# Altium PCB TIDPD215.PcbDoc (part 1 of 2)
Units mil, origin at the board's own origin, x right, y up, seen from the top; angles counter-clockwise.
Board outline 3200 x 2750 mil, 6 copper layers (Top Layer, Layer 2 - GND, Layer 3 - Power, Layer 4 - VPOS B/C, VNEG B/D, Layer 5 - VPOS A/D, VNEG A/C, Bottom Layer), stack 97.668 mil thick; 154 components, 79 nets, 389 pads, 279 vias.
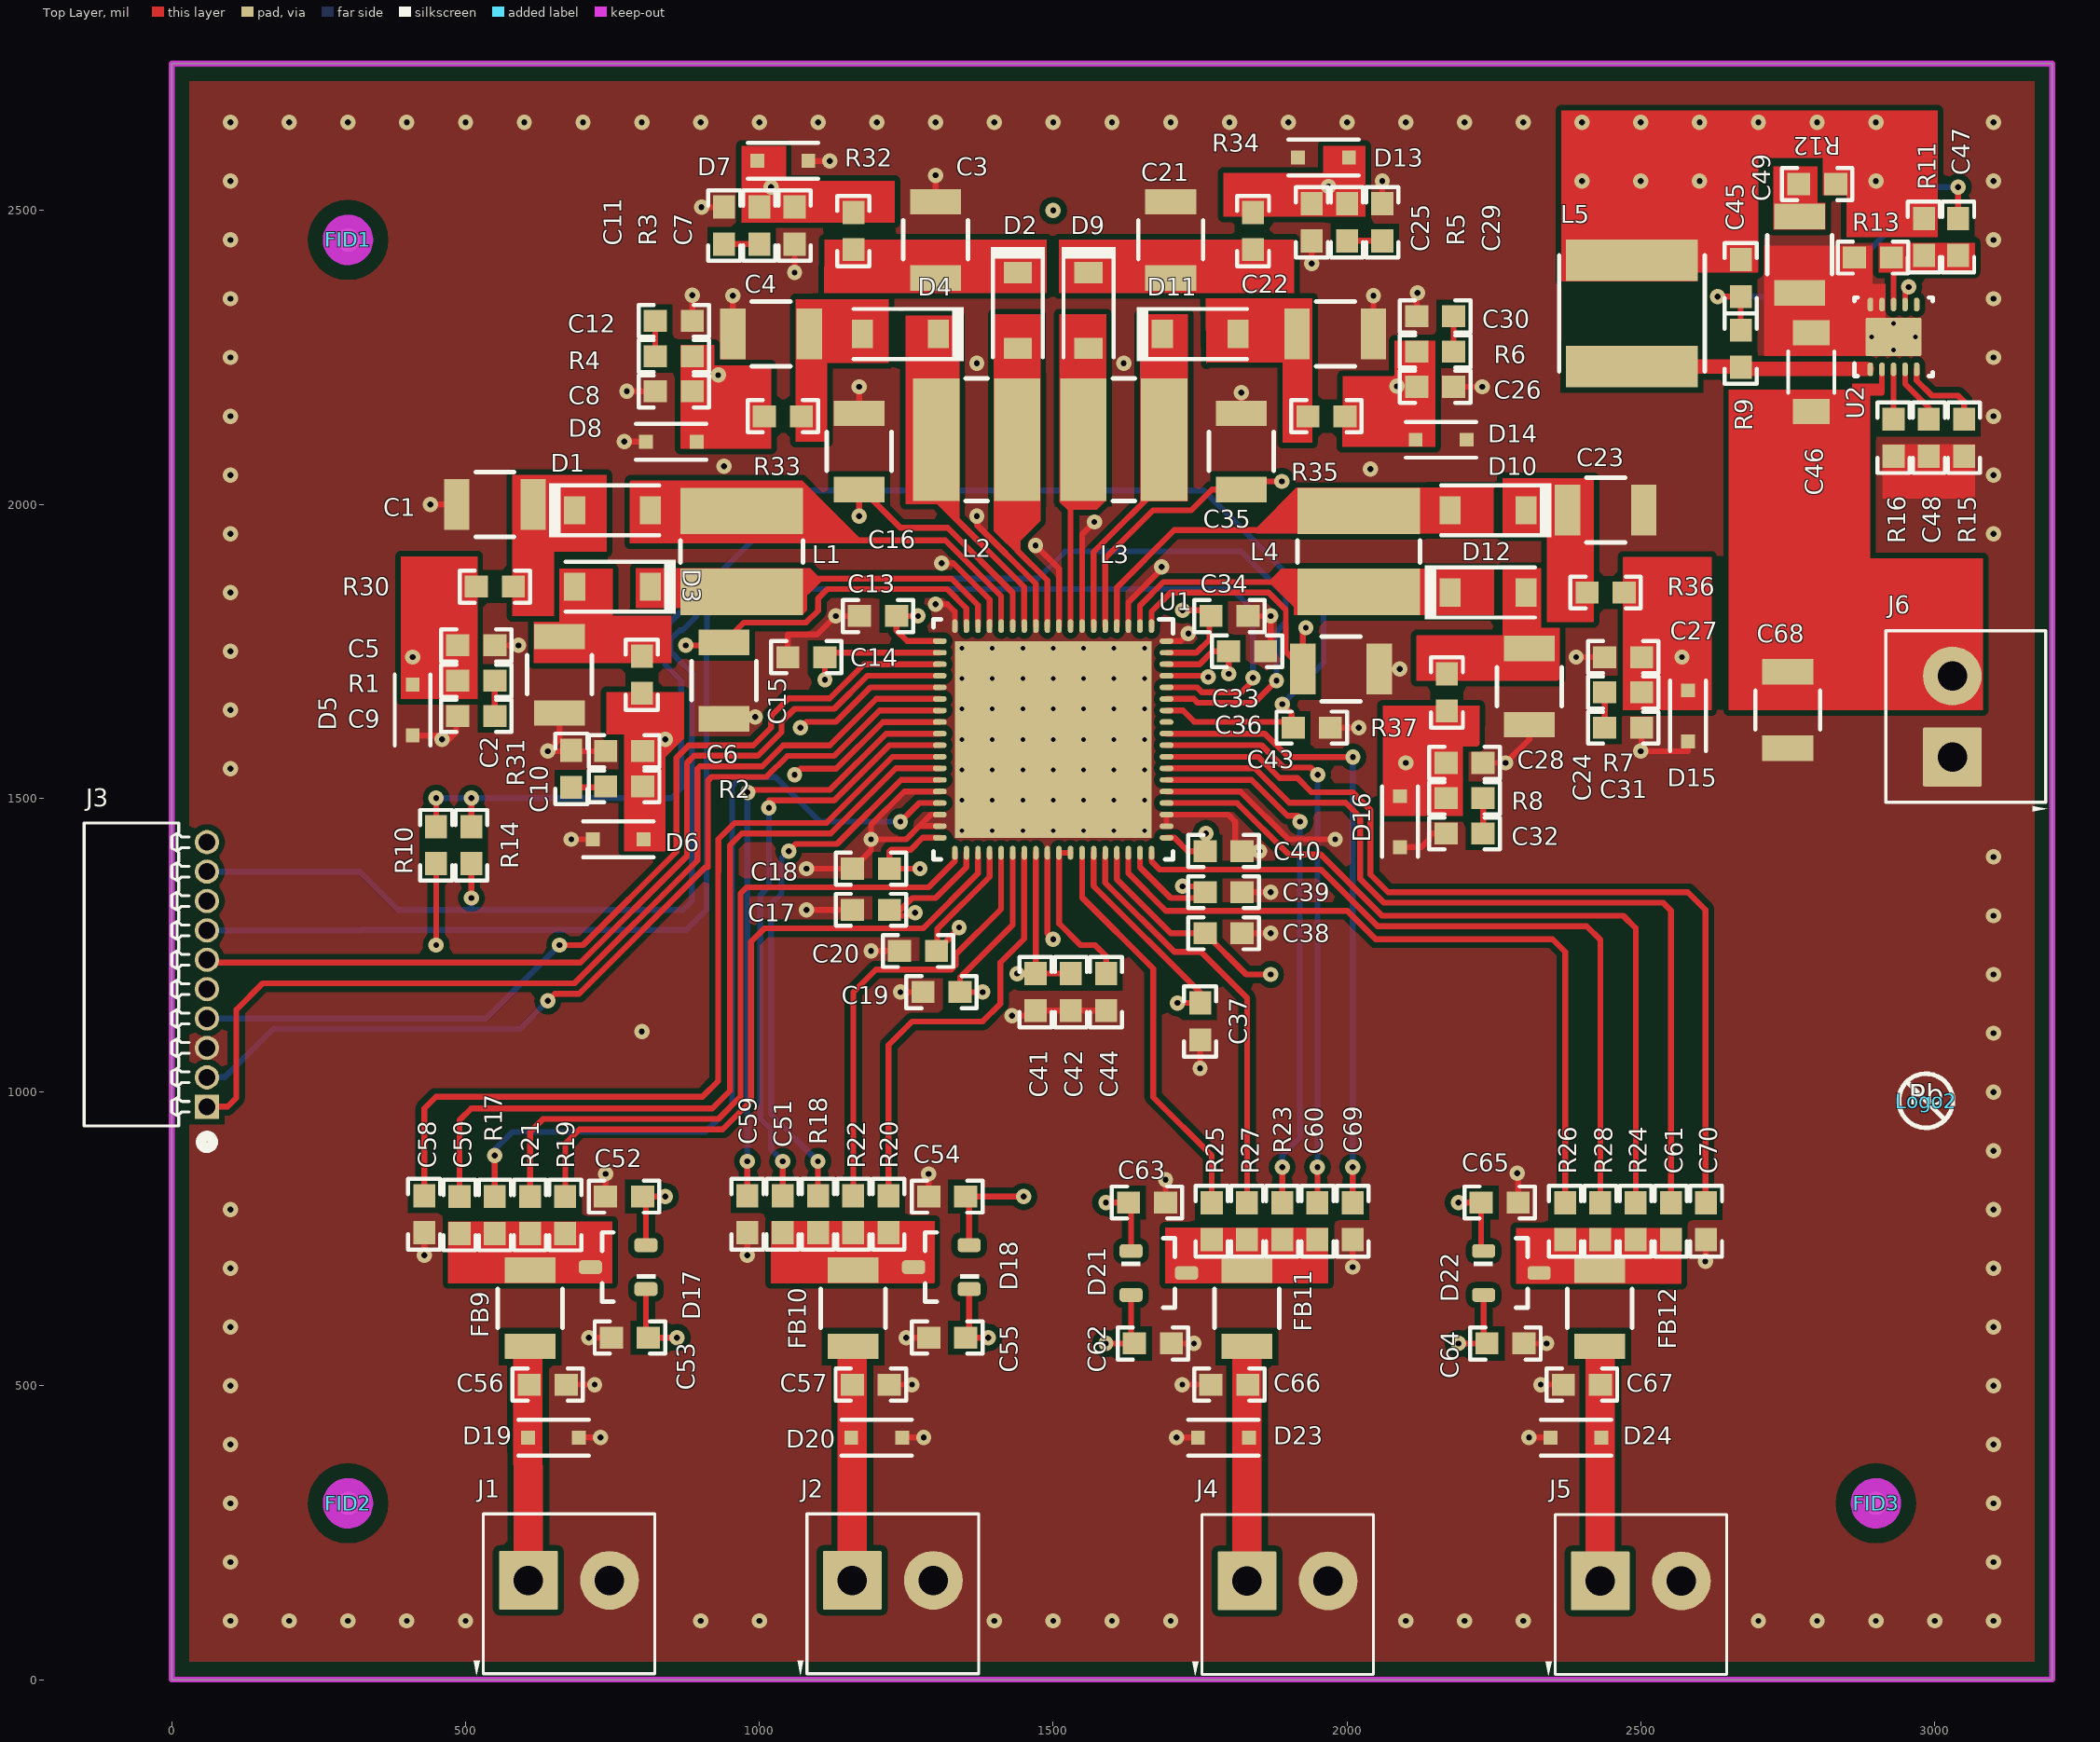
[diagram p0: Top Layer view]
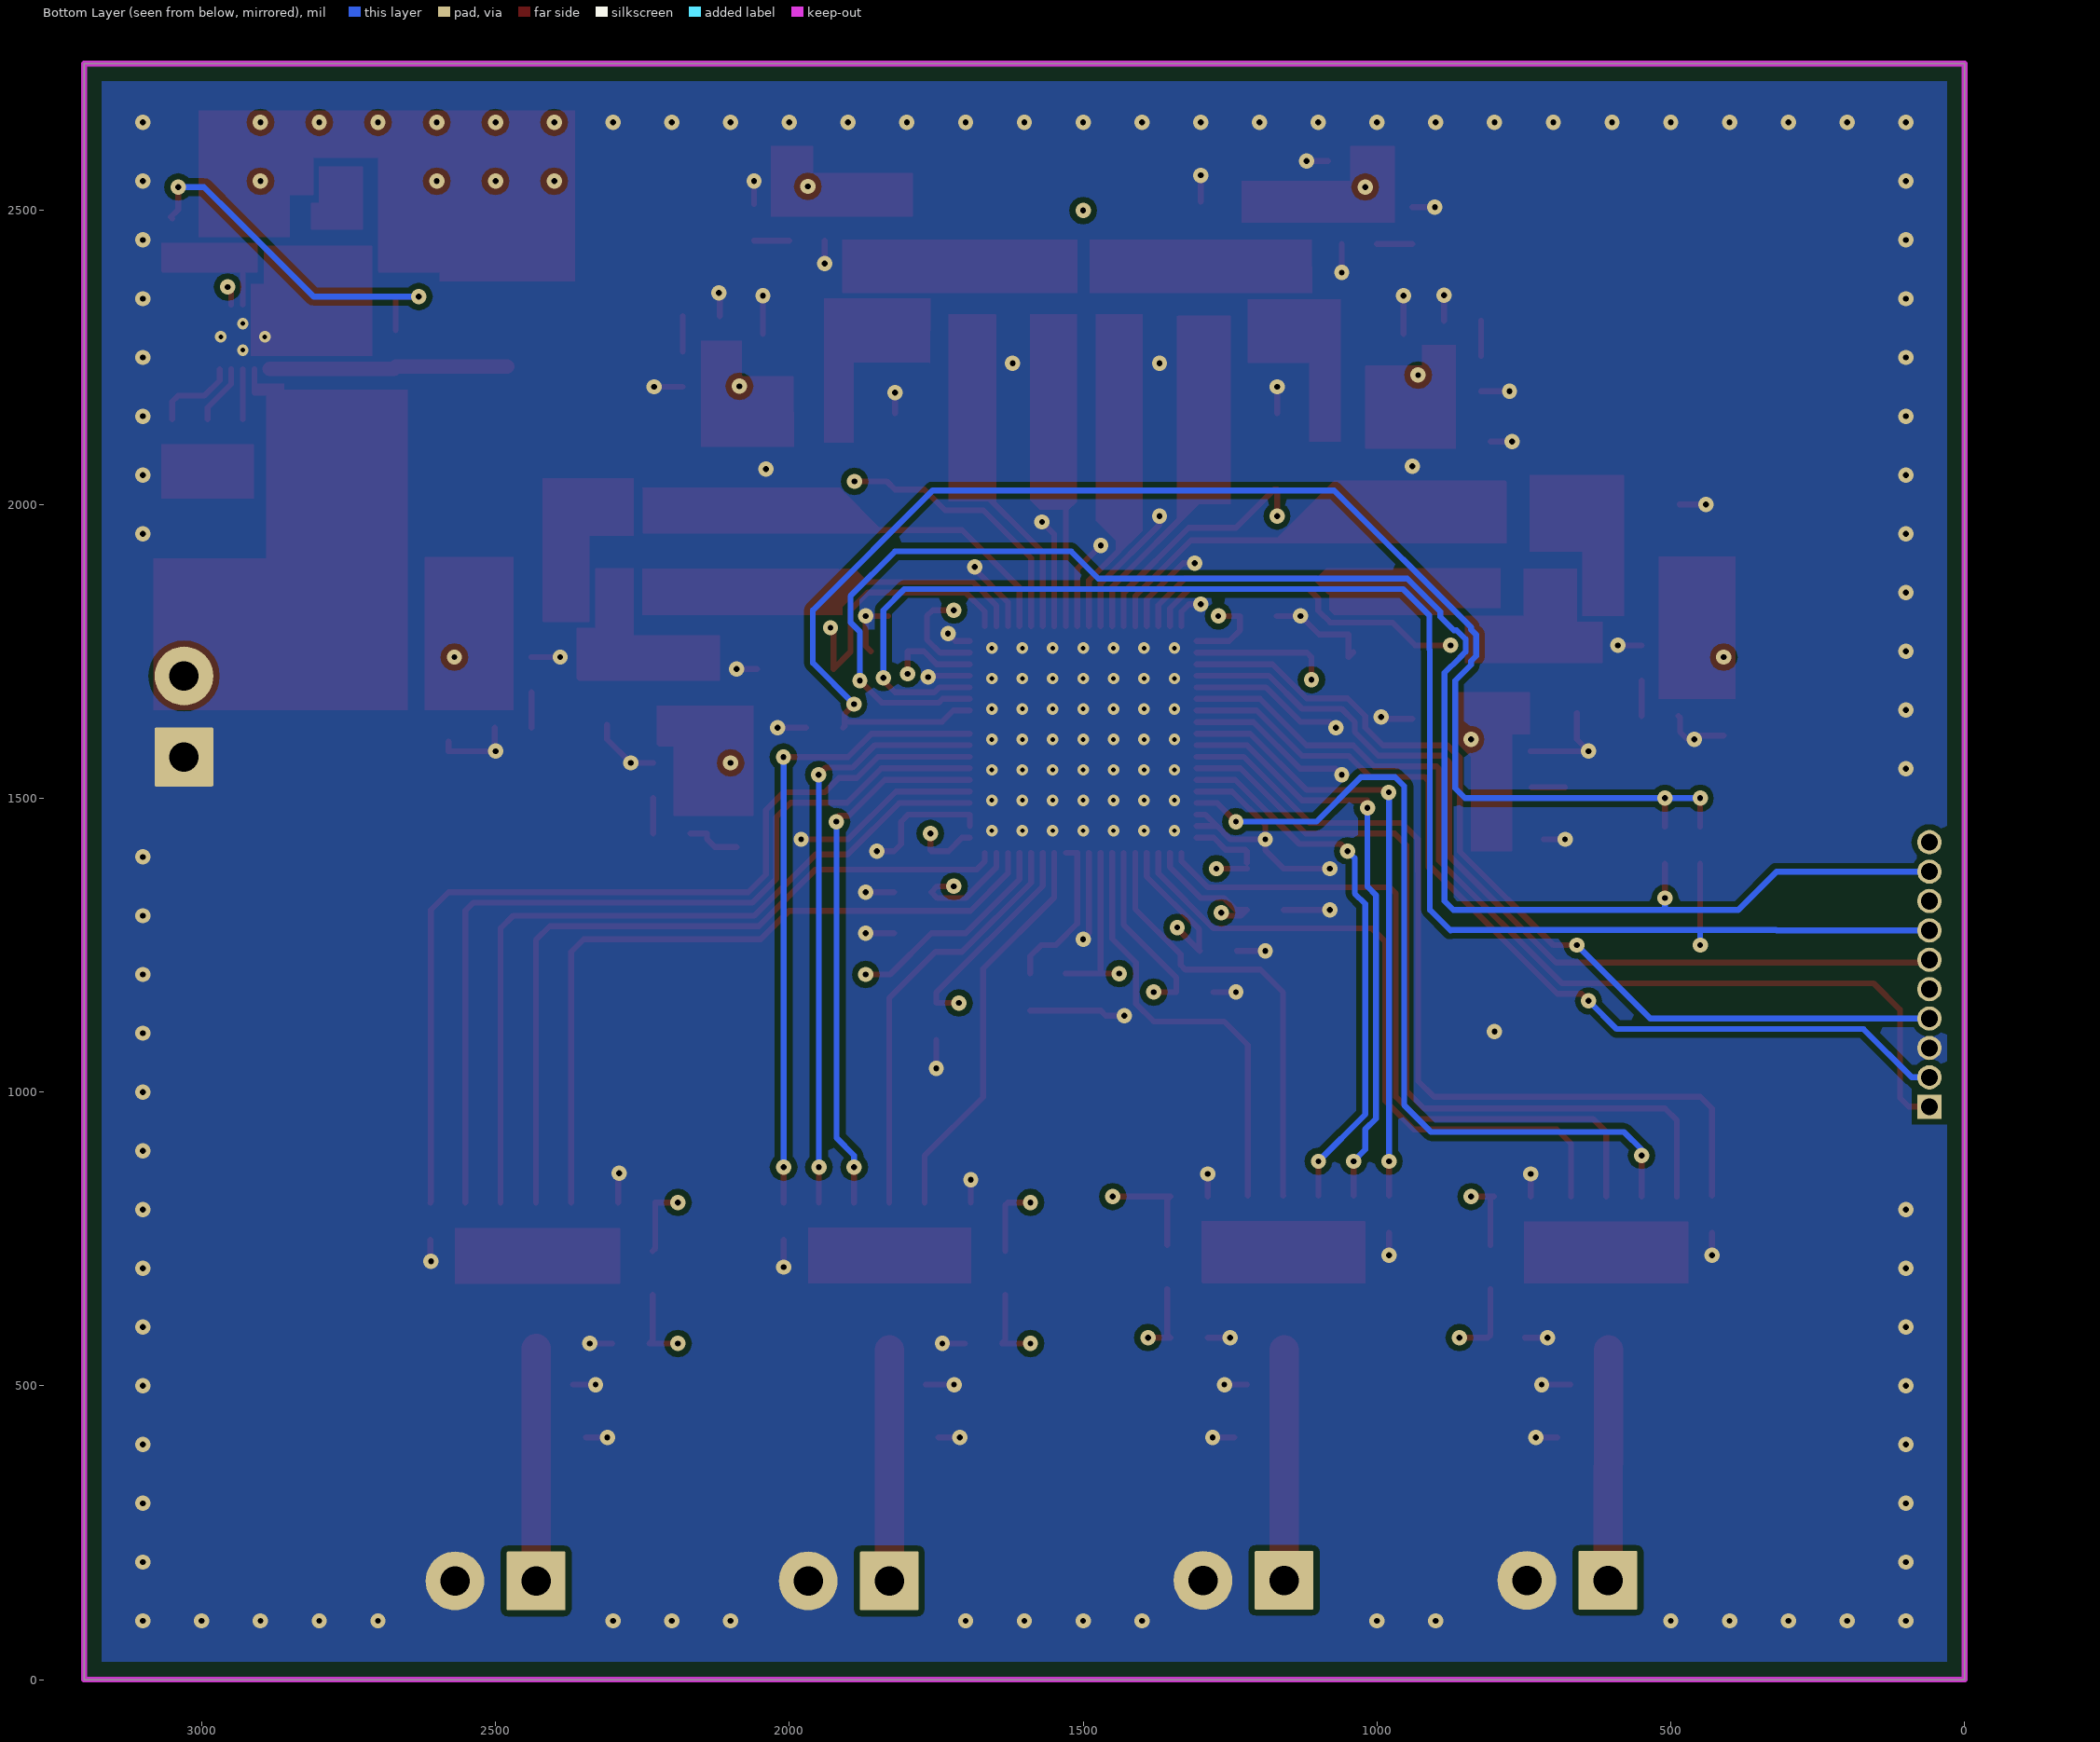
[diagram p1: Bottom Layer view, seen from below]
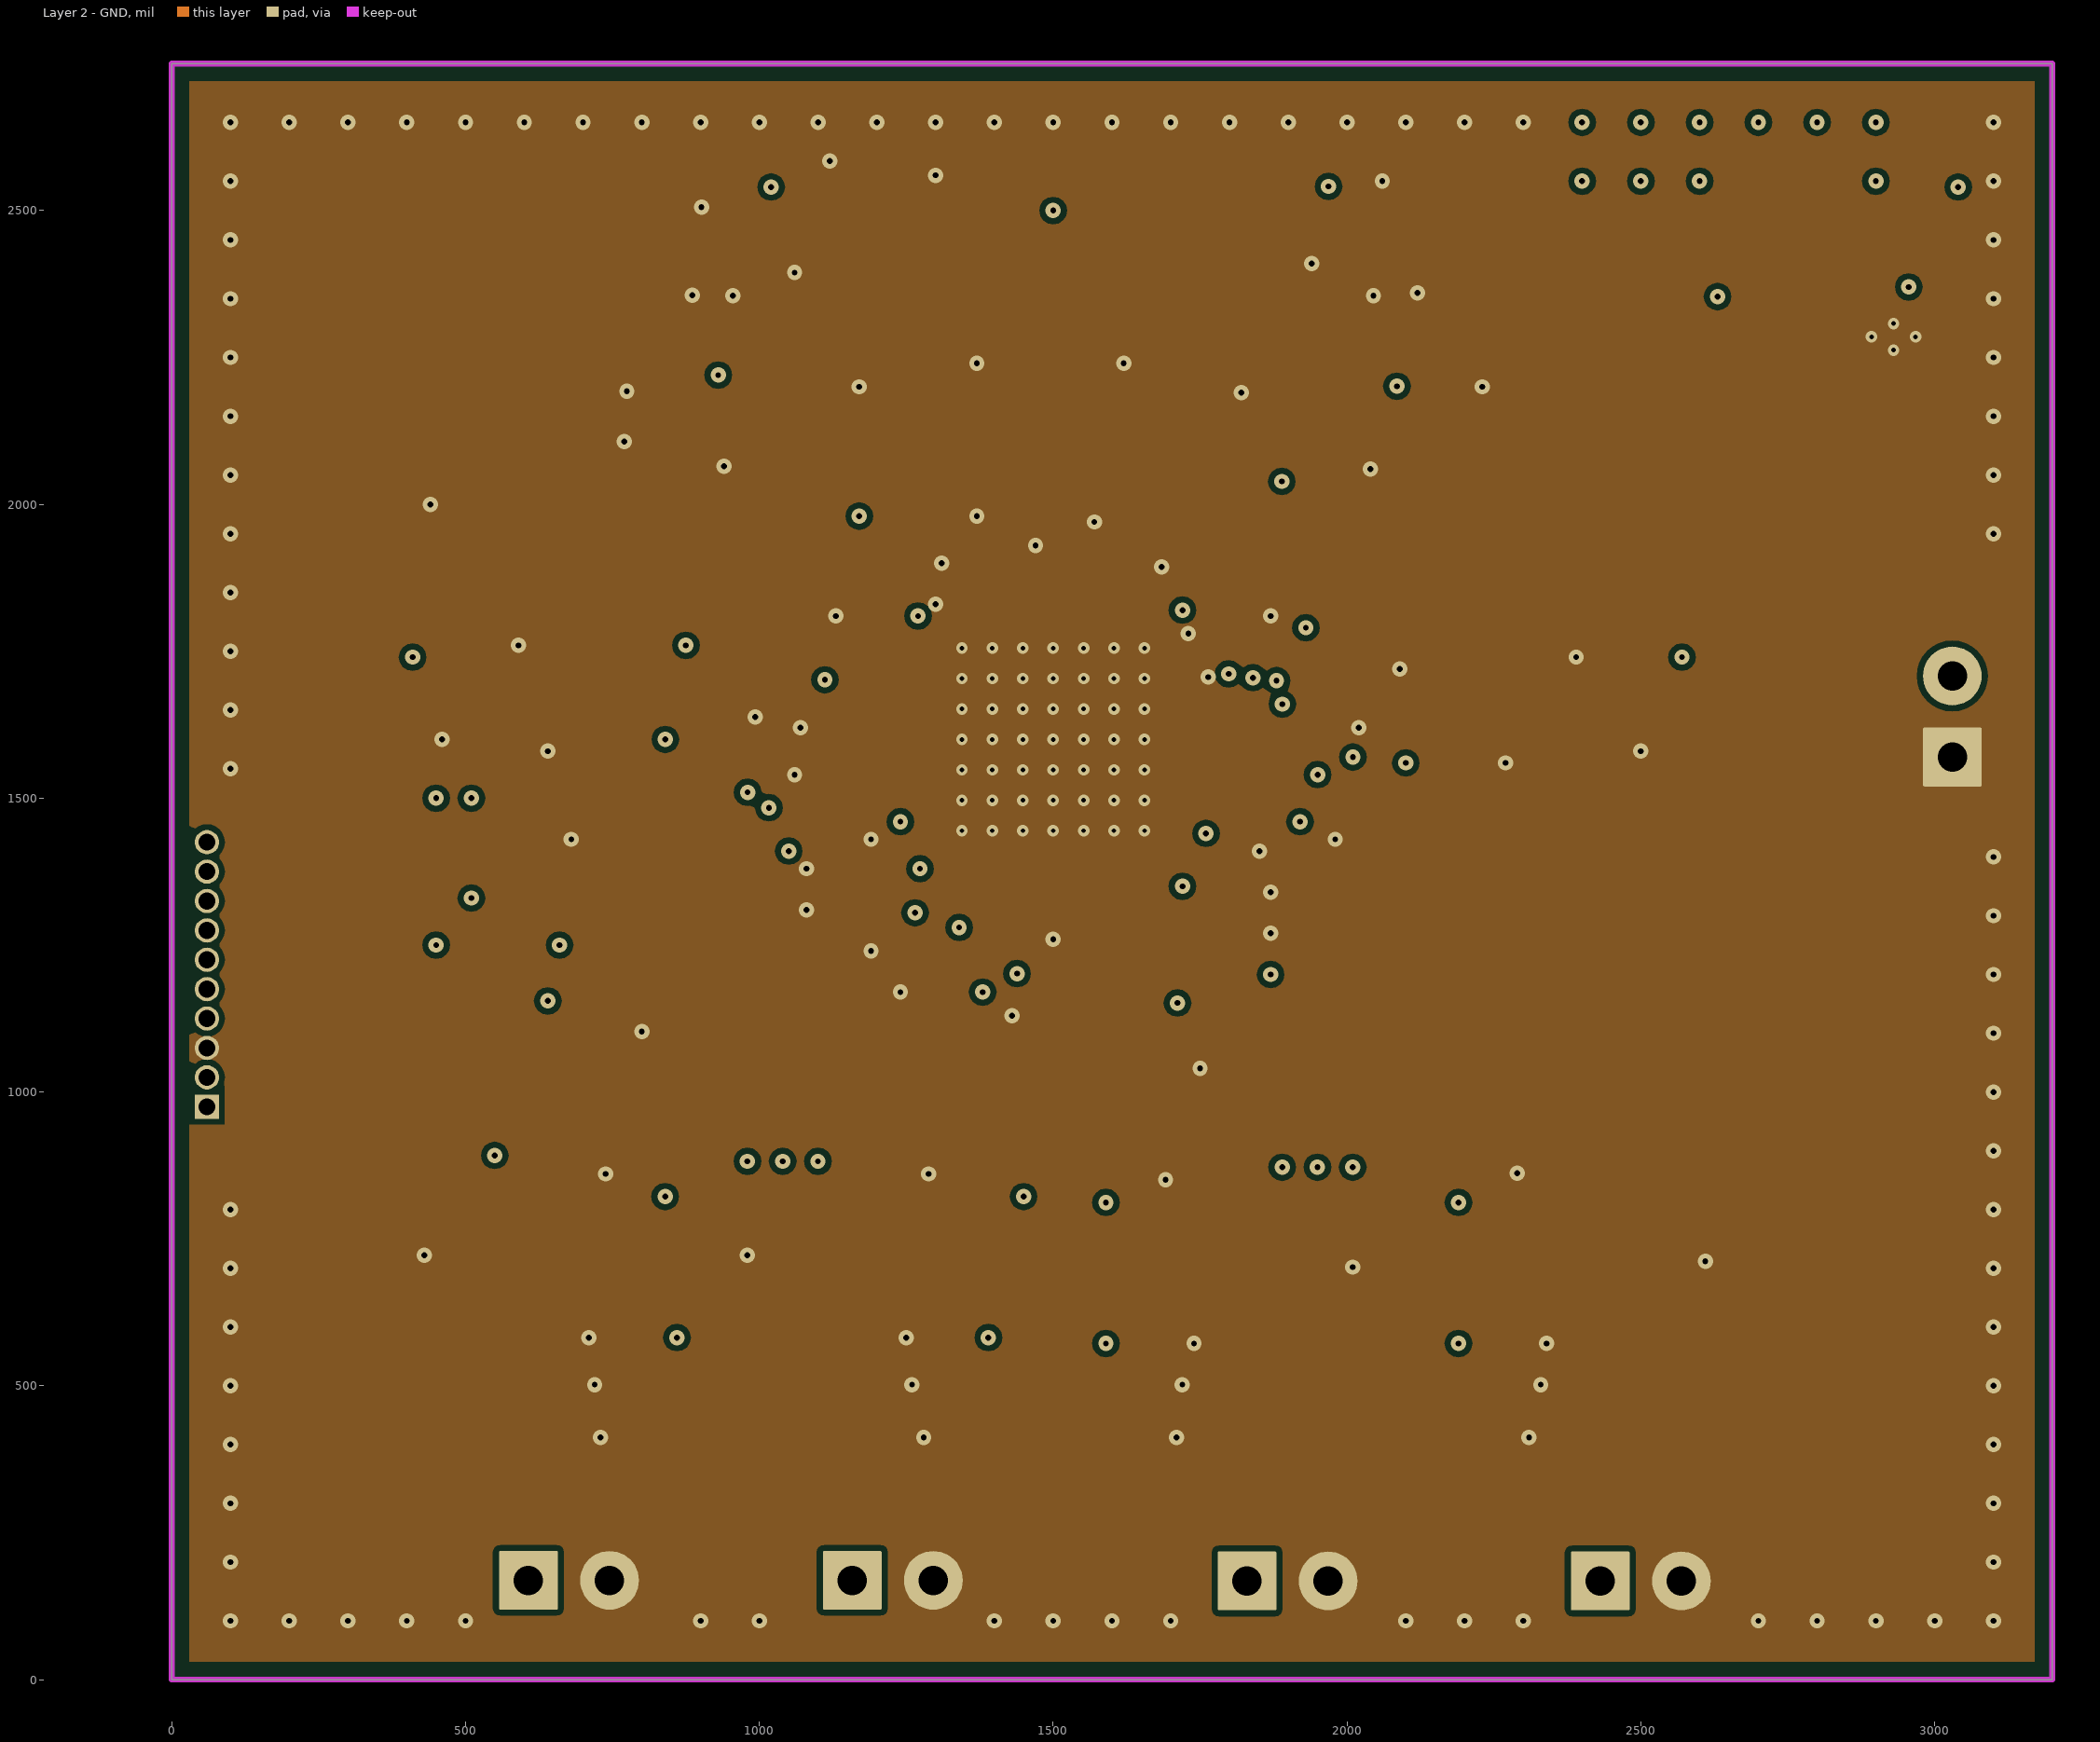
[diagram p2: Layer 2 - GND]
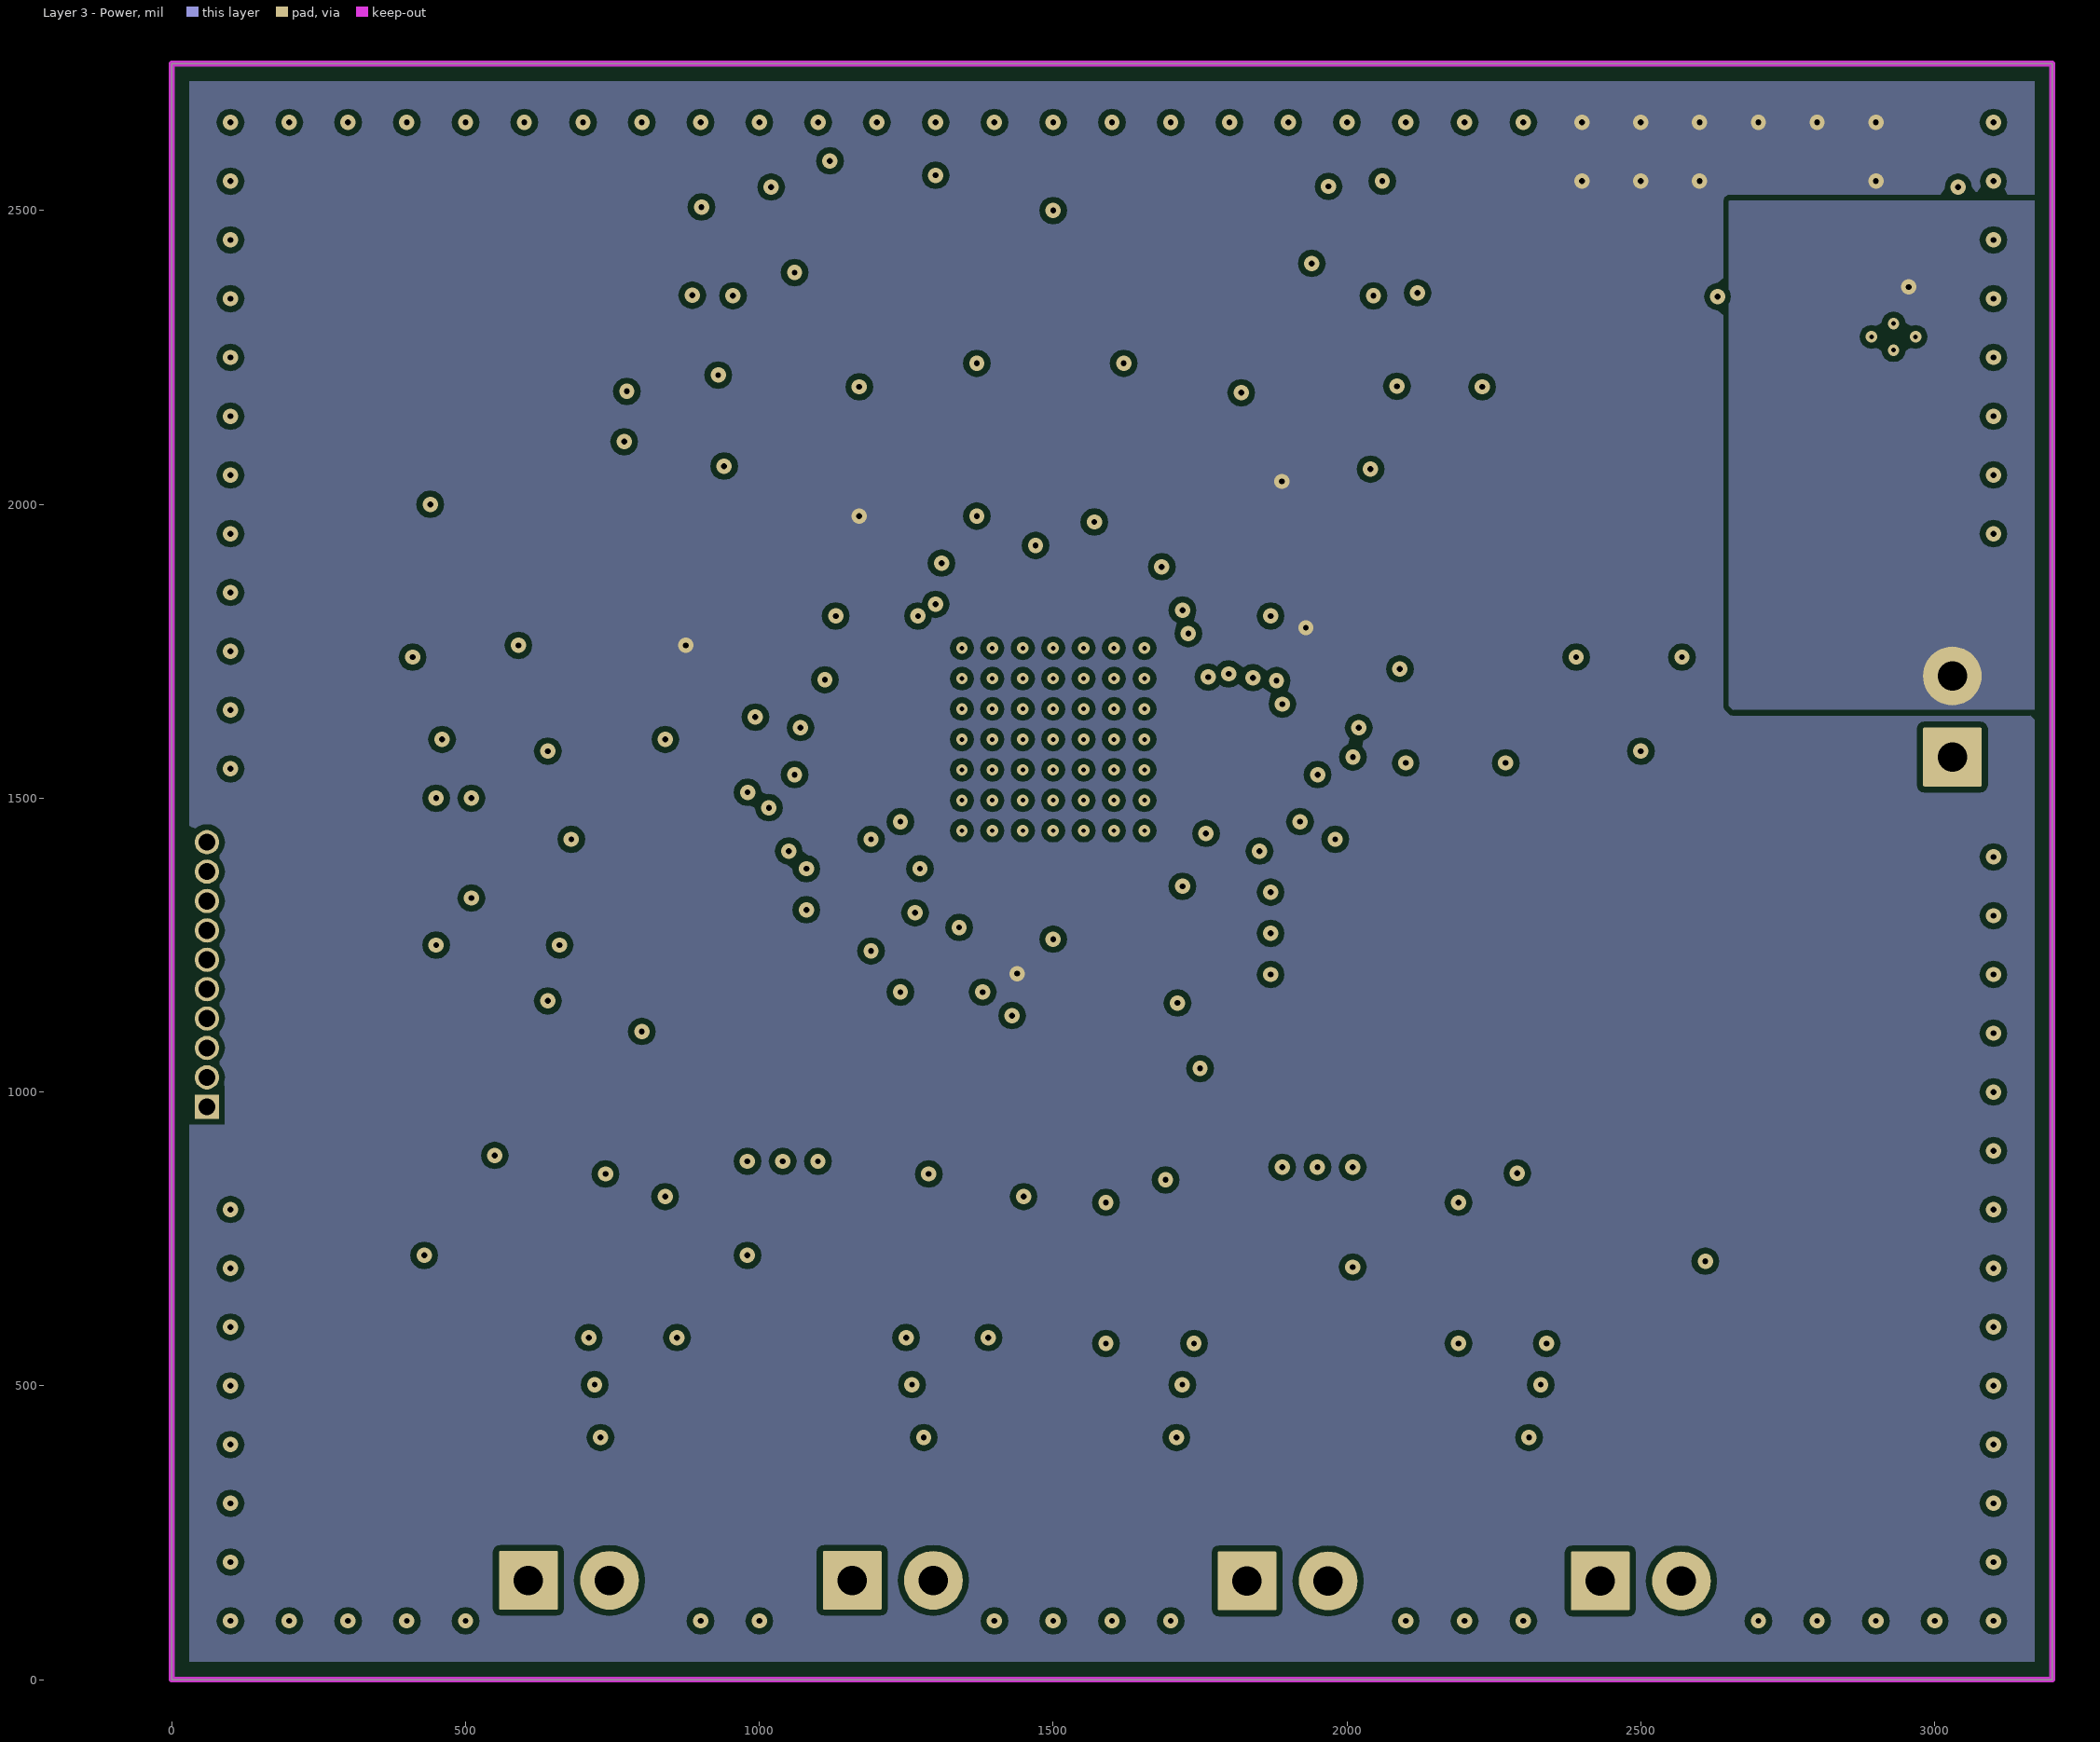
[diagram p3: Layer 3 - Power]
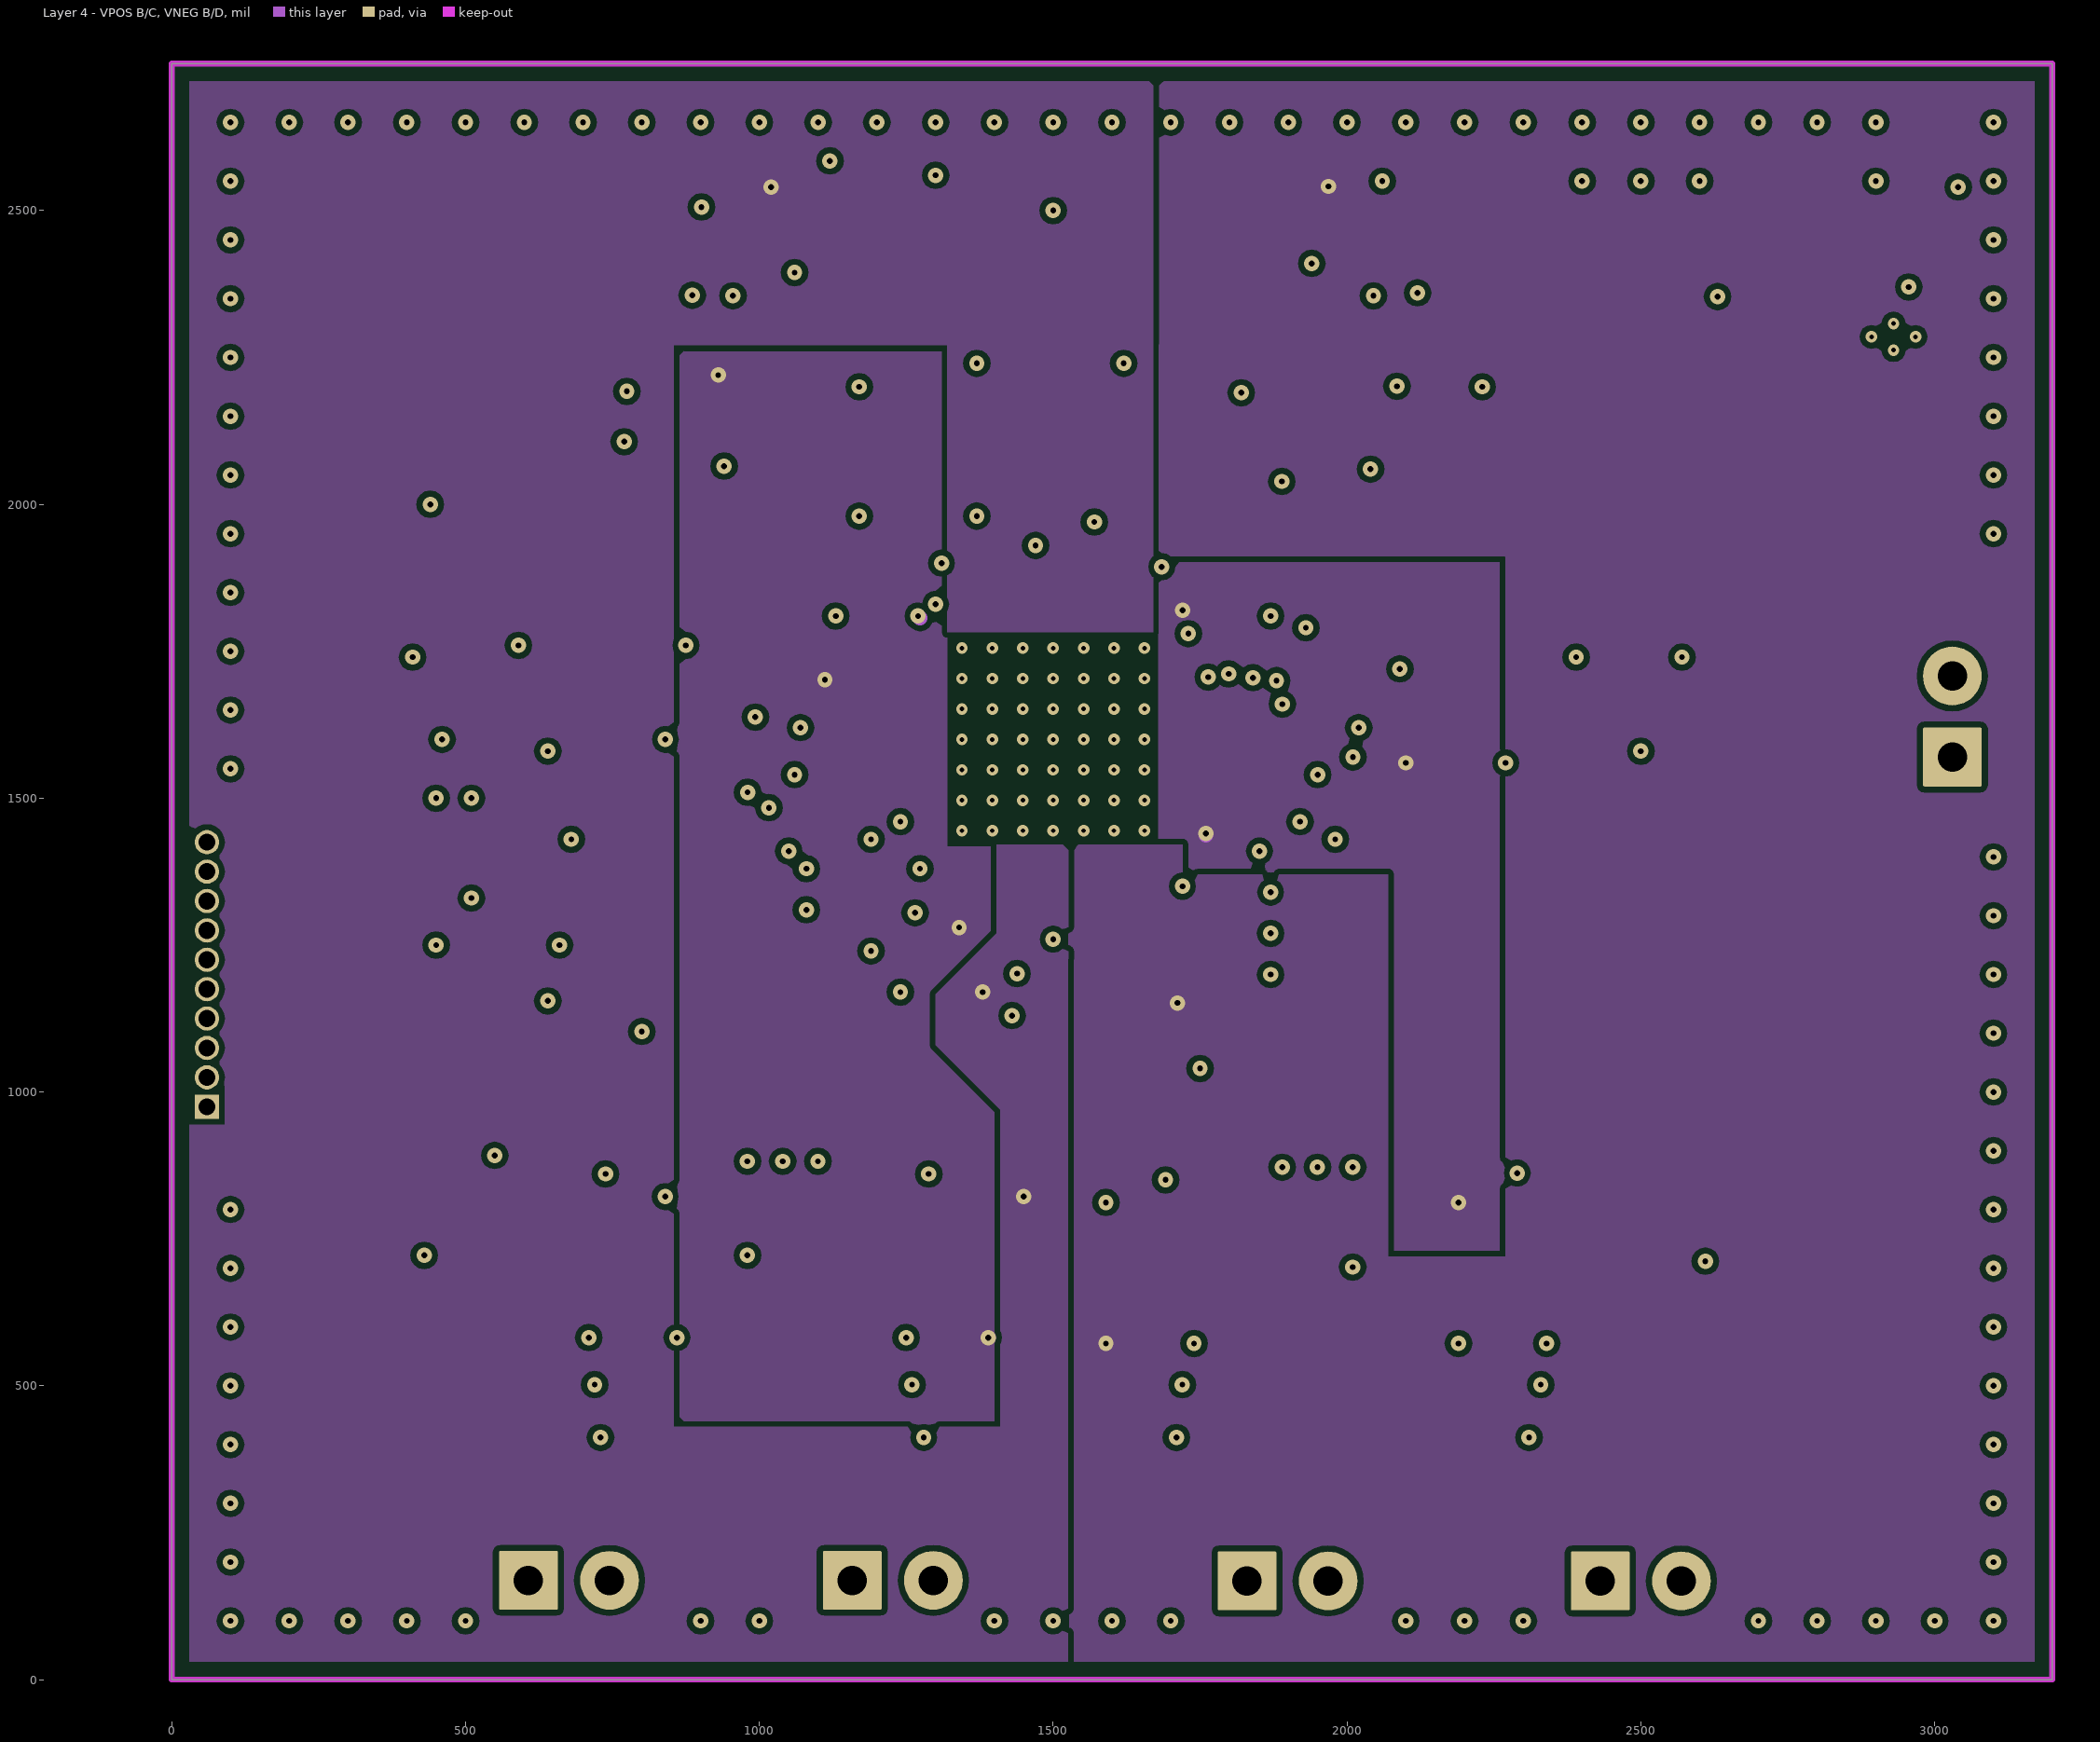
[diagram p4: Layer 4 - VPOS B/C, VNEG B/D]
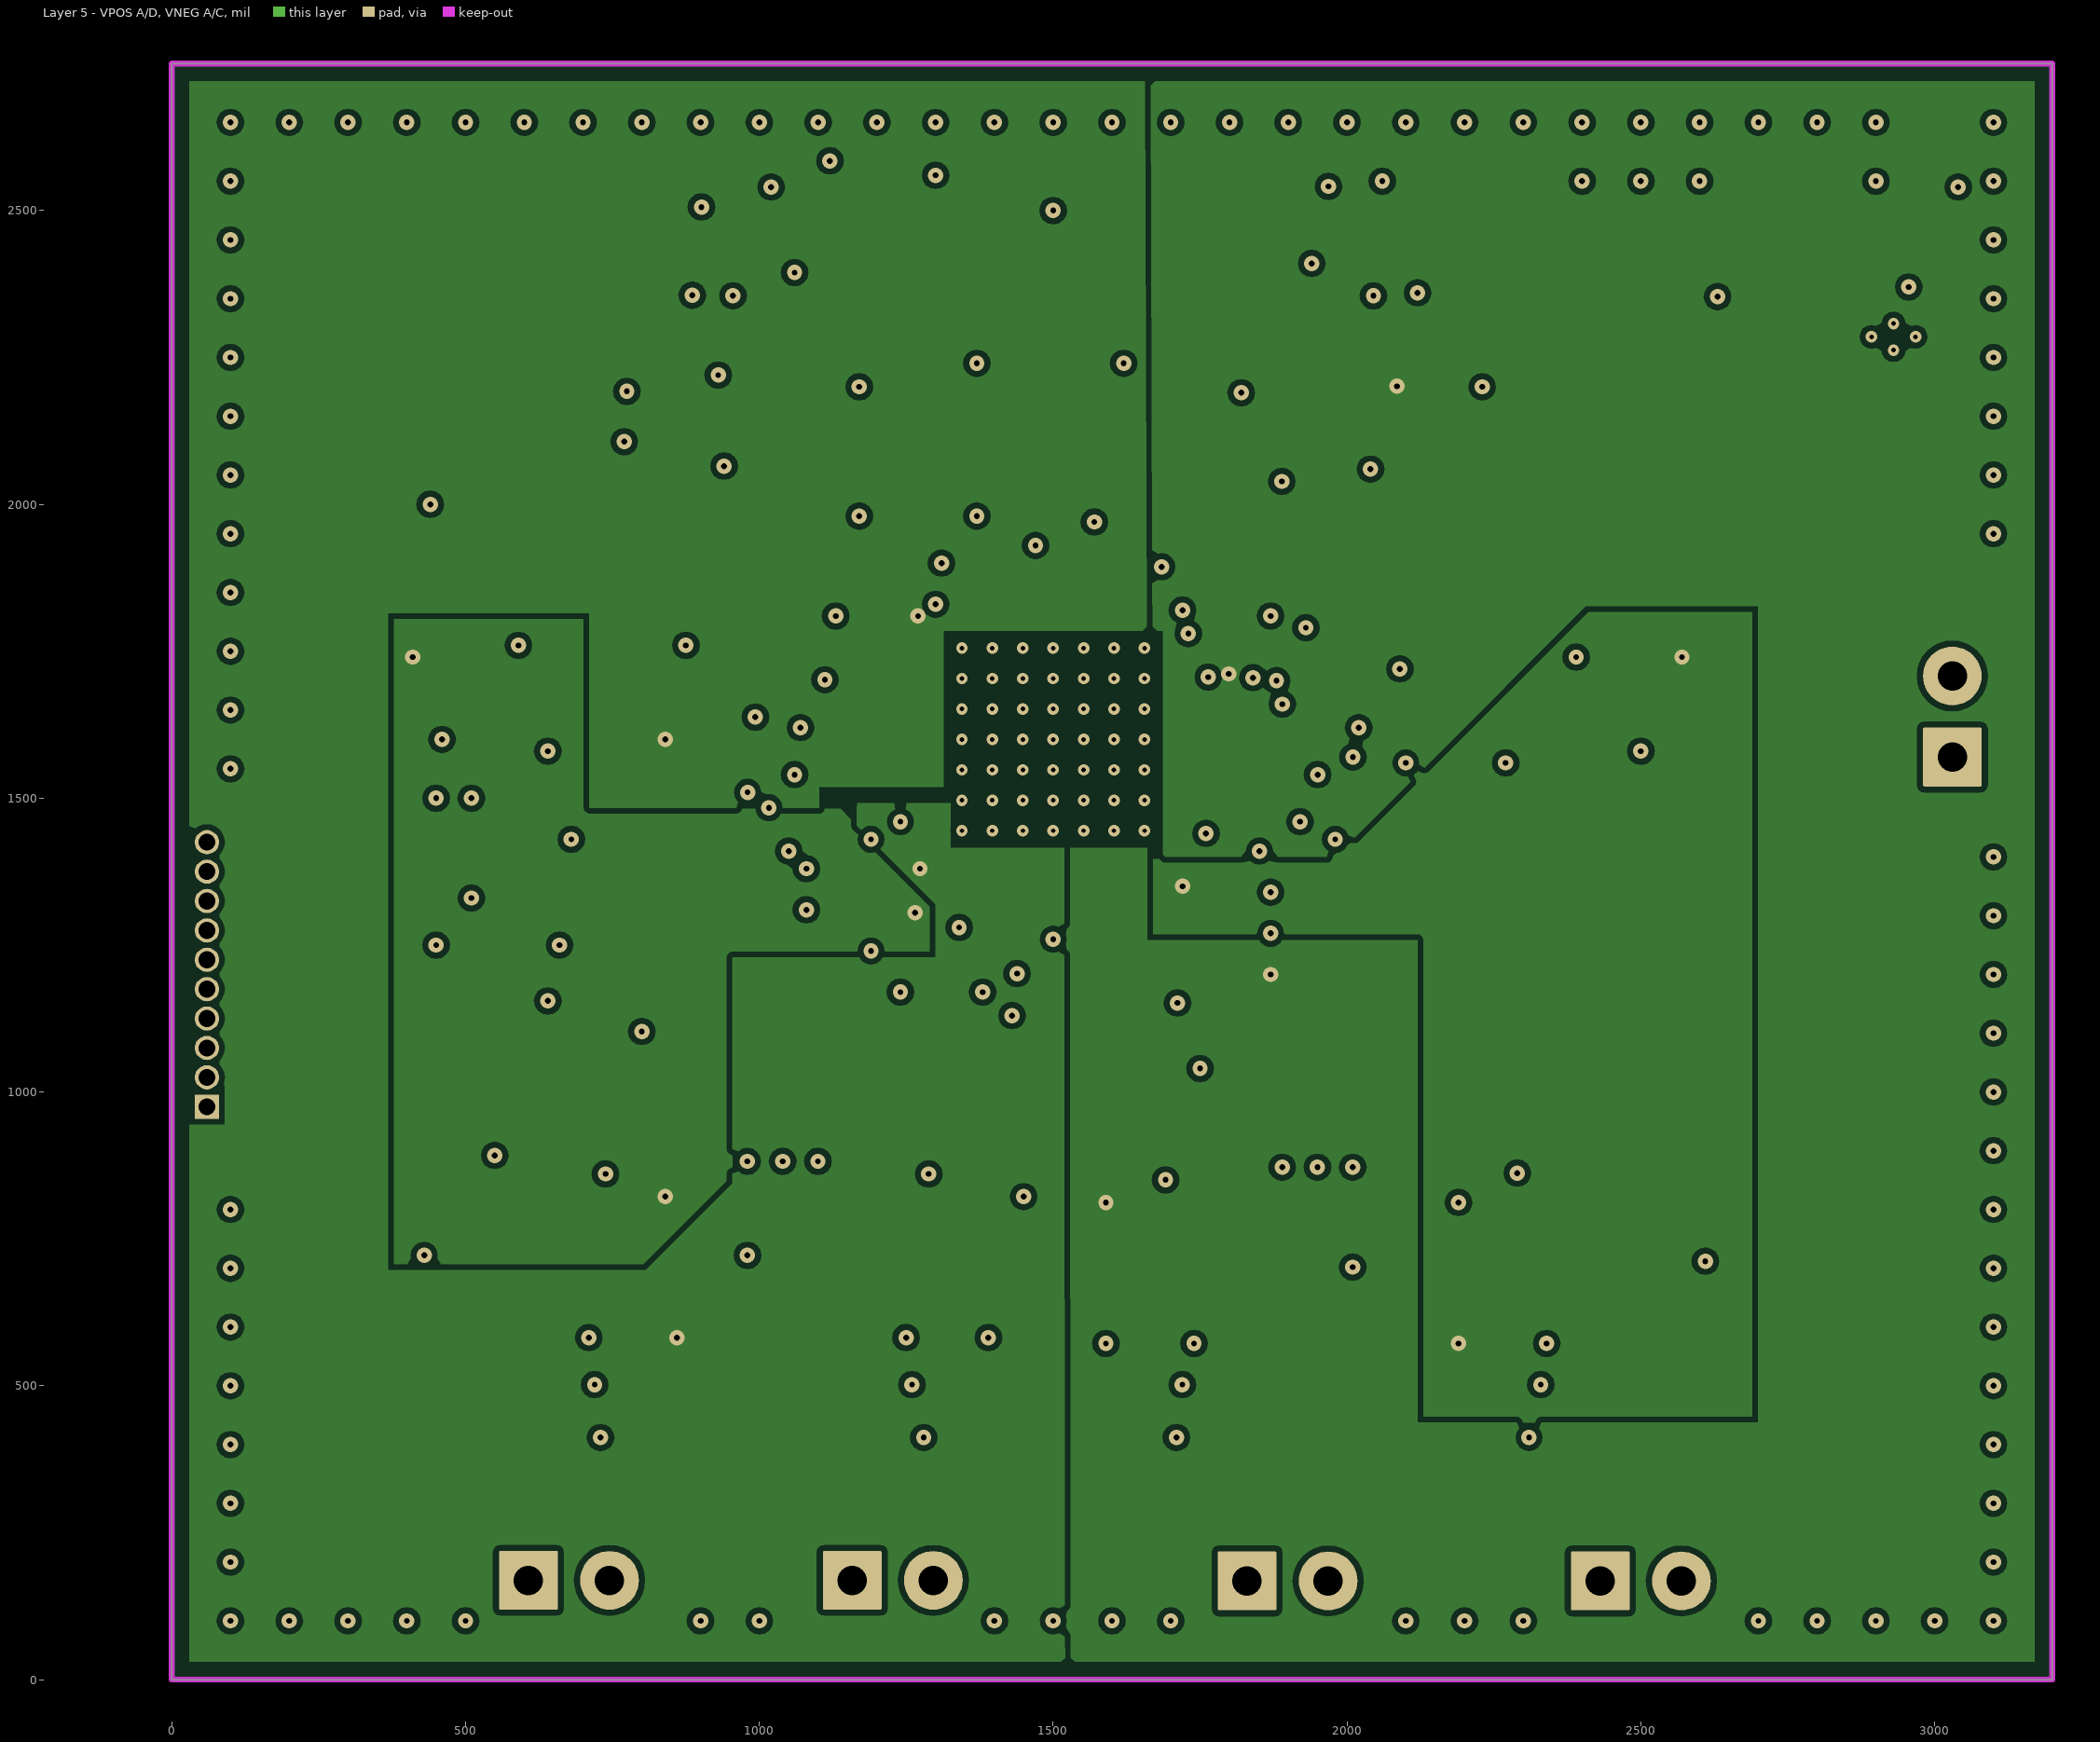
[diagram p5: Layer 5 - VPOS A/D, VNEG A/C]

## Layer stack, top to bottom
Top Solder: solder mask 0.4, Solder Resist, Dk 3.5
Top Layer: signal copper 1.4
Dielectric1: core 59.2, FR-4, Dk 4.8
Layer 2 - GND: signal copper 1.417
Dielectric 5: prepreg 5, Dk 4.2
Layer 3 - Power: signal copper 1.417
Dielectric 4: core 10, Dk 4.2
Layer 4 - VPOS B/C, VNEG B/D: signal copper 1.417
Dielectric 3: prepreg 5, Dk 4.2
Layer 5 - VPOS A/D, VNEG A/C: signal copper 1.417
Dielectric 2: core 10, Dk 4.2
Bottom Layer: signal copper 1.4
Bottom Solder: solder mask 0.4, Solder Resist, Dk 3.5

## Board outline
0,0 0,2750 3200,2750 3200,0

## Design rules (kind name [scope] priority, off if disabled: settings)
AcuteAngle [All] p1: minimum=2.50000000000000E+0001 checktracksonly=FALSE
AssemblyTestPointUsage [All] p1: valid=2
Clearance Clearance_Keepouts [((IsTrack Or IsArc) And Not InPoly) And IsFree and IsKeepOut vs ((IsTrack Or IsArc) And Not InPoly) And IsFree and IsKeepOut] p1: gap=0
Clearance Clearance_BoardEdge_MountingHoles [OnCopper and InComponentClass('Mounting Holes') vs IsKeepOut] p2: gap=40
Clearance Clearance_BoardEdge_Poly [OnCopper and InPoly vs IsKeepOut] p3: gap=25
Clearance Clearance_BoardEdge [OnCopper and Not InComponentClass('Logo') and not InComponentClass('FiducialMark') and not InRegion(1000,500,4000,800) and Not IsKeepout vs IsKeepOut] p4: gap=75
Clearance Clearance_Poly [InPolygon] p5: gap=10
Clearance [All] p6: gap=7.87
ComponentClearance ComponentClearance_MountingHoles_FiducialMarks [InComponentClass('Mounting Holes') vs InComponentClass('FiducialMark')] p1: gap=50 collisioncheckmode=3 verticalgap=10 showdistances=FALSE
ComponentClearance ComponentClearance_Shunt [InComponentClass('Header') vs InComponentClass('Shunt')] p2: gap=0 collisioncheckmode=3 verticalgap=0 showdistances=FALSE
ComponentClearance ComponentClearance_Logo [InComponentClass('Logo')] p3: gap=50 collisioncheckmode=3 verticalgap=10 showdistances=FALSE
ComponentClearance ComponentClearance_ScrewToNut [(HasFootprint('NY PMS 440 0025 PH')) vs (HasFootprint('Keystone_1902C'))] p4: gap=5 collisioncheckmode=3 verticalgap=10 showdistances=FALSE
ComponentClearance ComponentClearance_MountingHoles [InComponentClass('Mounting Holes')] p5: gap=250 collisioncheckmode=3 verticalgap=100000 showdistances=FALSE
ComponentClearance ComponentClearance_SmallPassives [HasFootprint('0201*') or HasFootprint('0402*') or HasFootprint('0508') or HasFootprint('0603*') or HasFootprint('0612') or HasFootprint('0805*') or HasFootprint('0815*') or HasFootprint('0830*') or HasFootprint('1206*') or HasFootprint('1210*') or HasFootprint('1808*') or HasFootprint('1812*') or HasFootprint('1825*') or HasFootprint('2010*') or HasFootprint('2220*') or HasFootprint('2225*') or HasFootprint('2512*') or HasFootprint('2728*') or HasFootprint('3518*') vs HasFootprint('0201*') or HasFootprint('0402*') or HasFootprint('0508') or HasFootprint('0603*') or HasFootprint('0612') or HasFootprint('0805*') or HasFootprint('0815*') or HasFootprint('0830*') or HasFootprint('1206*') or HasFootprint('1210*') or HasFootprint('1808*') or HasFootprint('1812*') or HasFootprint('1825*') or HasFootprint('2010*') or HasFootprint('2220*') or HasFootprint('2225*') or HasFootprint('2512*') or HasFootprint('2728*') or HasFootprint('3518*')] p6: gap=20 collisioncheckmode=3 verticalgap=10 showdistances=FALSE
ComponentClearance ComponentClearance_THtoSMT [IsThruComponent vs IsSMTComponent] p7: gap=100 collisioncheckmode=3 verticalgap=30 showdistances=FALSE
ComponentClearance ComponentClearance_THtoTH [IsThruComponent vs IsThruComponent] p8: gap=118.11 collisioncheckmode=3 verticalgap=30 showdistances=FALSE
ComponentClearance [All] p9: gap=40 collisioncheckmode=3 verticalgap=10 showdistances=FALSE
DiffPairsRouting [All] p1: maxlimit=100 minlimit=10 mostfreqgap=10 toplayer_minwidth=15 toplayer_maxwidth=15 toplayer_prefwidth=15 midlayer1_minwidth=15 midlayer1_maxwidth=15 midlayer1_prefwidth=15 midlayer2_minwidth=15 midlayer2_maxwidth=15 midlayer2_prefwidth=15 midlayer3_minwidth=15 midlayer3_maxwidth=15 midlayer3_prefwidth=15 midlayer4_minwidth=15 midlayer4_maxwidth=15 midlayer4_prefwidth=15 bottomlayer_minwidth=15 bottomlayer_maxwidth=15 bottomlayer_prefwidth=15 maxuncoupledlength=1000
FabricationTestPointUsage TestPointUsage [All] p1: valid=2 allowmultiple=FALSE
FabricationTestpoint Testpoint [All] p1: side=3 testpointundercomponent=TRUE minsize=40 maxsize=100 preferedsize=60 minholesize=0 maxholesize=40 preferedholesize=32 testpointgrid=1 allowsidetop=TRUE allowsidebottom=TRUE usegrid=TRUE gridtolerance=0.01
FanoutControl Fanout_LCC [IsLCC] p1: bgadir=Out bgaviamode=Centered fanoutstyle=Auto fanoutdirection=Alternating viagrid=1 // Fanout_LCC (Default Rule)
FanoutControl Fanout_BGA [IsBGA] p2: bgadir=Out bgaviamode=Centered fanoutstyle=Auto fanoutdirection=Alternating viagrid=1 // Fanout_BGA (Default Rule)
FanoutControl Fanout_Default [All] p4: bgadir=Out bgaviamode=Centered fanoutstyle=Auto fanoutdirection=Alternating viagrid=1 // Fanout_Default (Default Rule)
FanoutControl Fanout_Small [(CompPinCount < 5)] p5: bgadir=Out bgaviamode=Centered fanoutstyle=Auto fanoutdirection=OutThenIn viagrid=1 // Fanout_Small (Default Rule)
HoleSize [All] p1: absolutevalues=TRUE maxlimit=251 minlimit=7 maxpercent=80.000 minpercent=20.000
MinimumAnnularRing MinimumAnnularRing_ThermalPadVias [IsVia and InAnyComponent] p1: minimumring=5.91
MinimumAnnularRing [All] p2: minimumring=6
MinimumSolderMaskSliver MinimumSolderMaskSliver_Logo [InComponentClass('Logo') vs InComponentClass('Logo')] p1: minsoldermaskwidth=0.7
MinimumSolderMaskSliver [All] p2: minsoldermaskwidth=1.5
PlaneConnect [All] p1: planeconnectstyle=Direct reliefexpansion=10 reliefentries=4 reliefconductorwidth=10 reliefairgap=10
PolygonConnect [All] p1: connectstyle=Direct reliefconductorwidth=10 reliefentries=4 polygonreliefangle="90 Angle" airgapwidth=10
RoutingVias ThermalPadVias [IsVia and InAnyComponent] p1: holewidth=7.87 width=19.68 viastyle="Through Hole" minholewidth=7.87 minwidth=19.68 maxholewidth=12.99 maxwidth=23.62
RoutingVias [All] p2: holewidth=16 width=34 viastyle="Through Hole" minholewidth=7.87 minwidth=26 maxholewidth=40 maxwidth=65
SilkToBoardRegionClearance [Not ((IsComment or IsDesignator) And (Hide <> 'False')) and not InRegion(1000,500,4000,800)] p1:
SilkToSilkClearance SilkToSilkClearance_Pb-FreeLogo [(HasFootprint('Pb-Free_Overlay_Medium') OR HasFootprint('Pb-Free_Overlay_Small')) vs (HasFootprint('Pb-Free_Overlay_Medium') OR HasFootprint('Pb-Free_Overlay_Small'))] p1: silktosilkclearance=0
SilkToSilkClearance [All] p2: silktosilkclearance=4
SilkToSolderMaskClearance [IsPad] p1: minsilkscreentomaskgap=0 clearancetoexposedcopper=TRUE
SolderMaskExpansion [All] p1: expansion=1.97
Width [All] p1: maxlimit=100 minlimit=6 preferedwidth=10 checkconnectedcopper=TRUE
15 further rules are at their usual default settings.

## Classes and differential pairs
component class AssemblyNote: ZZ1 ZZ2 ZZ3
component class FiducialMark: FID1 FID2 FID3
component class TID_Hardware: FID1 FID2 FID3 Logo2 ZZ1 ZZ2 ZZ3
component class TIPD215_DAC8775SMPS: C1 C2 C3 C4 C5 C6 C7 C8 C9 C10 C11 C12 C13 C14 C15 C16 C17 C18 C19 C20 C21 C22 C23 C24 C25 C26 C27 C28 C29 C30 C31 C32 C33 C34 C35 C36 C37 C38 C39 C40 D1 D2 D3 D4 D5 D6 D7 D8 D9 D10 D11 D12 D13 D14 D15 D16 FB1 FB2 FB3 FB4 FB5 FB6 FB7 FB8 L1 L2 L3 L4 R1 R2 R3 R4 R5 R6 R7 R8 R30 R31 R32 R33 R34 R35 R36 R37
component class TIPD215_Device: C41 C42 C43 C44 C45 C46 C47 C48 C49 C50 C51 C52 C53 C54 C55 C56 C57 C58 C59 C60 C61 C62 C63 C64 C65 C66 C67 C68 C69 C70 D17 D18 D19 D20 D21 D22 D23 D24 FB9 FB10 FB11 FB12 J1 J2 J3 J4 J5 J6 L5 R9 R10 R11 R12 R13 R14 R15 R16 R17 R18 R19 R20 R21 R22 R23 R24 R25 R26 R27 R28 U1 U2

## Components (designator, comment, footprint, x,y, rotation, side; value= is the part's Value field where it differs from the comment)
C1 "UMK325AB7106KM-T" 1210_280 550,2000 r0 top
C2 "UMK325AB7106KM-T" 1210_280 660,1710 r270 top
C3 "UMK325AB7106KM-T" 1210_280 1300,2450 r270 top
C4 "UMK325AB7106KM-T" 1210_280 1020,2290 r180 top
C5 "GRM188R71H104KA93D" 0603 518.33,1760 r180 top
C6 "GRM188R71H104KA93D" 0603 770,1580 r180 top
C7 "GRM188R71H104KA93D" 0603 1060,2474.45 r90 top
C8 "GRM188R71H104KA93D" 0603 854.45,2192.29 r180 top
C9 "UMK107AB7105KA-T" 0603 518.33,1640 r0 top
C10 "UMK107AB7105KA-T" 0603 680,1550 r90 top
C11 "UMK107AB7105KA-T" 0603 940,2474.45 r270 top
C12 "UMK107AB7105KA-T" 0603 854.45,2312.29 r0 top
C13 "UMK107AB7105KA-T" 0603 1201.95,1810 r180 top
C14 "UMK107AB7105KA-T" 0603 1080,1740 r180 top
C15 "UMK325AB7106KM-T" 1210_280 940,1700 r270 top
C16 "UMK325AB7106KM-T" 1210_280 1170,2090 r90 top
C17 "UMK107AB7105KA-T" 0603 1190,1310 r0 top
C18 "UMK107AB7105KA-T" 0603 1190,1380 r180 top
C19 "UMK107AB7105KA-T" 0603 1310,1170 r0 top
C20 "UMK107AB7105KA-T" 0603 1270,1240 r180 top
C21 "UMK325AB7106KM-T" 1210_280 1700,2450 r270 top
C22 "UMK325AB7106KM-T" 1210_280 1980,2290 r0 top
C23 "UMK325AB7106KM-T" 1210_280 2440,1990 r180 top
C24 "UMK325AB7106KM-T" 1210_280 2310,1690 r270 top
C25 "GRM188R71H104KA93D" 0603 1940,2480 r90 top
C26 "GRM188R71H104KA93D" 0603 2150,2200 r0 top
C27 "GRM188R71H104KA93D" 0603 2470,1740 r0 top
C28 "GRM188R71H104KA93D" 0603 2200,1560 r0 top
C29 "UMK107AB7105KA-T" 0603 2060,2480 r270 top
C30 "UMK107AB7105KA-T" 0603 2150,2320 r180 top
C31 "UMK107AB7105KA-T" 0603 2470,1620 r180 top
C32 "UMK107AB7105KA-T" 0603 2200,1440 r180 top
C33 "UMK107AB7105KA-T" 0603 1830,1750 r0 top
C34 "UMK107AB7105KA-T" 0603 1800,1810 r0 top
C35 "UMK325AB7106KM-T" 1210_280 1820,2090 r90 top
C36 "UMK325AB7106KM-T" 1210_280 1990,1720 r0 top
C37 "UMK107AB7105KA-T" 0603 1750,1120 r90 top
C38 "UMK107AB7105KA-T" 0603 1790,1270 r0 top
C39 "UMK107AB7105KA-T" 0603 1790,1340 r180 top
C40 "UMK107AB7105KA-T" 0603 1790,1410 r0 top
C41 "GRM188R71H104KA93D" 0603 1470,1170 r90 top
C42 "UMK107AB7105KA-T" 0603 1530,1170 r90 top
C43 "GRM1885C1H201JA01D" 0603 1940,1620 r0 top
C44 "GRM188R71H104KA93D" 0603 1590,1170 r270 top
C45 "06031C332JAT2A" 0603 2670,2385 r270 top
C46 "CL31B225KCHSNNE" 1206_190 2790,2225 r90 top
C47 "GCM1885C2A101JA16D" 0603 3040,2455 r270 top
C48 "GRM188R71H333KA61D" 0603 2990,2113.35 r270 top
C49 "UMK325AB7106KM-T" 1210_280 2770,2425 r270 top
C50 "DNI" 0603 489.7,790.5 r90 top
C51 "DNI" 0603 1039.7,792 r90 top
C52 "UMK107AB7105KA-T" 0603 769.7,822 r0 top
C53 "UMK107AB7105KA-T" 0603 779.7,582 r0 top
C54 "UMK107AB7105KA-T" 0603 1319.7,822 r0 top
C55 "UMK107AB7105KA-T" 0603 1319.7,582 r0 top
C56 "GRM188R71H104KA93D" 0603 639.7,502 r0 top
C57 "GRM188R71H104KA93D" 0603 1189.7,502 r0 top
C58 "C1608X7R1H224K080AB" 0603 429.7,792 r90 top
C59 "C1608X7R1H224K080AB" 0603 979.7,792 r90 top
C60 "DNI" 0603 1949.7,780.05 r90 top
C61 "DNI" 0603 2551.02,780.05 r90 top
C62 "UMK107AB7105KA-T" 0603 1669.7,572 r180 top
C63 "UMK107AB7105KA-T" 0603 1659.7,812 r180 top
C64 "UMK107AB7105KA-T" 0603 2269.7,572 r180 top
C65 "UMK107AB7105KA-T" 0603 2259.7,812 r180 top
C66 "GRM188R71H104KA93D" 0603 1799.7,502 r180 top
C67 "GRM188R71H104KA93D" 0603 2399.7,502 r180 top
C68 "UMK325AB7106KM-T" 1210_280 2750,1650 r270 top
C69 "C1608X7R1H224K080AB" 0603 2009.7,780.05 r90 top
C70 "C1608X7R1H224K080AB" 0603 2611.02,780.05 r90 top
D1 "MBRX160-TP" SOD-123 750,1990 r0 top
D2 "MBRX160-TP" SOD-123 1440,2330 r270 top
D3 "MBRX160-TP" SOD-123 750,1860 r180 top
D4 "MBRX160-TP" SOD-123 1240,2290 r180 top
D5 "CDSOD323-T36SC" SOD-323-Bi 410,1650 r90 top
D6 "CDSOD323-T36SC" SOD-323-Bi 760,1430 r0 top
D7 "CDSOD323-T36SC" SOD-323-Bi 1040,2584.45 r180 top
D8 "CDSOD323-T36SC" SOD-323-Bi 850,2106.69 r0 top
D9 "MBRX160-TP" SOD-123 1560,2330 r270 top
D10 "MBRX160-TP" SOD-123 2240,1990 r180 top
D11 "MBRX160-TP" SOD-123 1750,2290 r0 top
D12 "MBRX160-TP" SOD-123 2240,1850 r0 top
D13 "CDSOD323-T36SC" SOD-323-Bi 1960,2590 r0 top
D14 "CDSOD323-T36SC" SOD-323-Bi 2160,2110 r180 top
D15 "CDSOD323-T36SC" SOD-323-Bi 2580,1640 r90 top
D16 "CDSOD323-T36SC" SOD-323-Bi 2090,1460 r90 top
D17 "BAV99-7-F" SOT-23 759.7,702 r180 top
D18 "BAV99-7-F" SOT-23 1309.7,702 r180 top
D19 "CDSOD323-T36SC" SOD-323-Bi 649.7,412 r180 top
D20 "CDSOD323-T36SC" SOD-323-Bi 1199.7,412 r180 top
D21 "BAV99-7-F" SOT-23 1679.7,692 r0 top
D22 "BAV99-7-F" SOT-23 2279.7,692 r0 top
D23 "CDSOD323-T36SC" SOD-323-Bi 1789.7,412 r0 top
D24 "CDSOD323-T36SC" SOD-323-Bi 2389.7,412 r0 top
FB9 "FBMH3225HM601NT" 1210_280 609.7,632 r270 top
FB10 "FBMH3225HM601NT" 1210_280 1159.7,632 r270 top
FB11 "FBMH3225HM601NT" 1210_280 1829.7,632 r270 top
FB12 "FBMH3225HM601NT" 1210_280 2429.7,632 r270 top
FID1 "Fiducial" Fiducial10-20 300,2450 r0 top
FID2 "Fiducial" Fiducial10-20 300,300 r0 top
FID3 "Fiducial" Fiducial10-20 2900,300 r0 top
J1 "ED555/2DS" TERM_BLK_ED555-2DS 607,169 r0 top
J2 "ED555/2DS" TERM_BLK_ED555-2DS 1158,169 r0 top
J3 "SUPER MINI DIG FEMALE" CONN_851-43-010-20-001000 60,1200 r270 top
J4 "ED555/2DS" TERM_BLK_ED555-2DS 1830,168 r0 top
J5 "ED555/2DS" TERM_BLK_ED555-2DS 2431,168 r0 top
J6 "ED555/2DS" TERM_BLK_ED555-2DS 3030,1570 r90 top
L1 "74408943101" WE-SPC_4838 970,1920 r270 top
L2 "74408943101" WE-SPC_4838 1370,2110 r180 top
L3 "74408943101" WE-SPC_4838 1620,2110 r0 top
L4 "74408943101" WE-SPC_4838 2020,1920 r270 top
L5 "74404064100" WE-LQS_6045 2485,2325 r90 top
Logo2 "Pb-Free Symbol" Pb-Free_Overlay_Small 2985,985 r0 top
R1 "CRCW060310R0FKEA" 0603 518.33,1700 r180 top
R2 "CRCW060310R0FKEA" 0603 770,1520 r180 top
R3 "CRCW060310R0FKEA" 0603 1000,2474.45 r90 top
R4 "CRCW060310R0FKEA" 0603 854.45,2252.29 r180 top
R5 "CRCW060310R0FKEA" 0603 2000,2480 r90 top
R6 "CRCW060310R0FKEA" 0603 2150,2260 r0 top
R7 "CRCW060310R0FKEA" 0603 2470,1680 r0 top
R8 "CRCW060310R0FKEA" 0603 2200,1500 r0 top
R9 "CRCW0603487KFKEA" 0603 2670,2265 r90 top
R10 "CRCW060310K0JNEA" 0603 450,1420 r90 top
R11 "CRCW0603301KFKEA" 0603 2981.77,2455 r90 top
R12 "CRCW06030000Z0EA" 0603 2800,2545 r0 top
R13 "CRCW060334K0FKEA" 0603 2895,2420 r0 top
R14 "CRCW060310K0JNEA" 0603 510,1420 r90 top
R15 "CRCW0603301KFKEA" 0603 3050,2113.35 r90 top
R16 "CRCW06030000Z0EA" 0603 2930,2113.35 r90 top
R17 "CRCW060315R0JNEA" 0603 549.7,790.5 r270 top
R18 "CRCW060315R0JNEA" 0603 1099.7,792 r270 top
R19 "CRCW060315R0JNEA" 0603 669.7,790.5 r270 top
R20 "CRCW060315R0JNEA" 0603 1219.7,792 r270 top
R21 "CRCW060315R0JNEA" 0603 609.7,790.5 r270 top
R22 "CRCW060315R0JNEA" 0603 1159.7,792 r270 top
R23 "CRCW060315R0JNEA" 0603 1889.7,780.05 r270 top
R24 "CRCW060315R0JNEA" 0603 2491.02,780.05 r270 top
R25 "CRCW060315R0JNEA" 0603 1769.7,780.05 r270 top
R26 "CRCW060315R0JNEA" 0603 2371.02,780.05 r270 top
R27 "CRCW060315R0JNEA" 0603 1829.7,780.05 r270 top
R28 "CRCW060315R0JNEA" 0603 2431.02,780.05 r270 top
R30 "CRCW060310R0FKEA" 0603 550,1860 r0 top
R31 "CRCW060310R0FKEA" 0603 800,1710 r90 top
R32 "CRCW060310R0FKEA" 0603 1160,2465 r270 top
R33 "CRCW060310R0FKEA" 0603 1040,2150 r0 top
R34 "CRCW060310R0FKEA" 0603 1840,2465 r270 top
R35 "CRCW060310R0FKEA" 0603 1965,2150 r180 top
R36 "CRCW060310R0FKEA" 0603 2440,1850 r180 top
R37 "CRCW060310R0FKEA" 0603 2170,1680 r90 top
U1 "DAC8775RMP" RMP0072A 1500,1600 r270 top
U2 "LM5166QDRCQ1" DRC0010J 2930,2285 r90 top
ZZ1 "These assemblies are ESD sensitive, ESD precautions shall be observed." AssemblyNote 185,3238.11 r0 top
ZZ2 "These assemblies must be clean and free from flux and all contaminants. Use of no clean flux is not acceptable." AssemblyNote 185,3149.56 r0 top
ZZ3 "These assemblies must comply with workmanship standards IPC-A-610 Class 2, unless otherwise specified." AssemblyNote 185,3061 r0 top

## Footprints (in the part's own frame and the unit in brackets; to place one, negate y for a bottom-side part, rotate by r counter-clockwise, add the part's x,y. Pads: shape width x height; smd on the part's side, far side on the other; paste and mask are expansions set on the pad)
0603 [mm] "0603 from SM-752 data"
  rect 1x0.95 smd: 1(-0.8,0) 2(0.8,0)
  silkscreen extent -1.52,-0.69 1.52,0.69, body extent -0.87,-0.47 0.87,0.47, height 1
1206_190 [mm] "1206_190"
  rect 1.1x1.6 smd: 1(-1.7,0) 2(1.7,0)
  silkscreen extent -0.9,-1 0.9,1, body extent -1.75,-0.95 1.75,0.95, height 1.9
1210_280 [mm] "SMD, 2-Leads, Body 3.6x2.8mm, Height 2.8mm"
  rect 1.1x2.2 smd: 1(-1.65,0) 2(1.65,0)
  silkscreen extent -0.84,-1.4 0.84,1.4, body extent -1.8,-1.4 1.8,1.4, height 2.8
AssemblyNote [mil] "Assembly Note"
CONN_851-43-010-20-001000 [mm] "Mill-max"
  rect 1.05x1.05 hole 0.73 mask+0.06: 1(5.715,0)
  round 1.05 hole 0.73 mask+0.06: 2(4.445,0) 3(3.175,0) 4(1.905,0) 5(0.635,0) 6(-0.635,0) 7(-1.905,0) 8(-3.175,0) 9(-4.445,0) 10(-5.715,0)
  silkscreen extent -6.54,-5.31 7.49,0.25, body extent -6.54,-5.31 6.54,0.23, height 2.23
DRC0010J [mm] "SON, 10-Leads, Body 3x3mm, Pitch 0.5mm, Thermal Pad 2.4x1.65mm, TI Recommended"
  rrect100% 0.6x0.24 smd: 1(-1.4,1) 2(-1.4,0.5) 3(-1.4,0) 4(-1.4,-0.5) 5(-1.4,-1) 6(1.4,-1) 7(1.4,-0.5) 8(1.4,0) 9(1.4,0.5) 10(1.4,1)
  rrect6% 1.65x2.4 smd paste-0.825: 11(0,0)
  silkscreen extent -1.7,-1.7 1.7,1.7, body extent -1.5,-1.5 1.5,1.5, height 0.77
Fiducial10-20 [mm]
  round 1 smd mask+0.5: 1(0,0)
  Top Layer keep-out circle w1.178: c0,0 r0.5
Pb-Free_Overlay_Small [mil]
  silkscreen extent -46,-46 46,46
RMP0072A [mm] "QFN, 72-Leads, Body 10.1x10.1mm, Pitch 0.5mm"
  oval 0.6x0.24 smd mask+0.07: 1(-4.9,4.25) 2(-4.9,3.75) 3(-4.9,3.25) 4(-4.9,2.75) 5(-4.9,2.25) 6(-4.9,1.75) 7(-4.9,1.25) 8(-4.9,0.75) 9(-4.9,0.25) 10(-4.9,-0.25) 11(-4.9,-0.75) 12(-4.9,-1.25) 13(-4.9,-1.75) 14(-4.9,-2.25) 15(-4.9,-2.75) 16(-4.9,-3.25) 17(-4.9,-3.75) 18(-4.9,-4.25) 37(4.9,-4.25) 38(4.9,-3.75) 39(4.9,-3.25) 40(4.9,-2.75) 41(4.9,-2.25) 42(4.9,-1.75) 43(4.9,-1.25) 44(4.9,-0.75) 45(4.9,-0.25) 46(4.9,0.25) 47(4.9,0.75) 48(4.9,1.25) 49(4.9,1.75) 50(4.9,2.25) 51(4.9,2.75) 52(4.9,3.25) 53(4.9,3.75) 54(4.9,4.25)
  oval 0.24x0.6 smd mask+0.07: 19(-4.25,-4.9) 20(-3.75,-4.9) 21(-3.25,-4.9) 22(-2.75,-4.9) 23(-2.25,-4.9) 24(-1.75,-4.9) 25(-1.25,-4.9) 26(-0.75,-4.9) 27(-0.25,-4.9) 28(0.25,-4.9) 29(0.75,-4.9) 30(1.25,-4.9) 31(1.75,-4.9) 32(2.25,-4.9) 33(2.75,-4.9) 34(3.25,-4.9) 35(3.75,-4.9) 36(4.25,-4.9) 55(4.25,4.9) 56(3.75,4.9) 57(3.25,4.9) 58(2.75,4.9) 59(2.25,4.9) 60(1.75,4.9) 61(1.25,4.9) 62(0.75,4.9) 63(0.25,4.9) 64(-0.25,4.9) 65(-0.75,4.9) 66(-1.25,4.9) 67(-1.75,4.9) 68(-2.25,4.9) 69(-2.75,4.9) 70(-3.25,4.9) 71(-3.75,4.9) 72(-4.25,4.9)
  rect 8.5x8.5 smd paste-4.5 mask+0.07: 73(0,0)
  silkscreen extent -5.18,-5.18 5.18,5.18, body extent -5.05,-5.05 5.05,5.05, height 1.01
SOD-123 [mm] "On Semi recommended land pattern"
  rect 0.915x1.22 smd: 1(-1.637,0) 2(1.637,0)
  silkscreen extent -2.74,-1.17 2.03,1.17, body extent -1.93,-0.9 1.93,0.9, height 1.35
SOD-323-Bi [mm] "SOD323, 2-Leads, Body 1.9x1.45mm, No Polarity Mark"
  rect 0.6x0.6 smd paste-0.05: 1(-1.1,0) 2(1.1,0)
  silkscreen extent -1.53,-0.77 1.53,0.77, body extent -1.27,-0.65 1.27,0.65, height 1.02
SOT-23 [mm] "SOT23, 3-Leads, Body 2.9x1.3mm, Pitch 0.95mm, Lead Span 2.5mm, IPC Medium Density"
  rrect50% 1x0.6 smd: 1(-1.2,0.95) 2(-1.2,-0.95) 3(1.2,0)
  silkscreen extent -1.62,-1.5 0.7,1.5, body extent -1.16,-1.45 1.21,1.45, height 1
TERM_BLK_ED555-2DS [mil]
  rrect4% 100x100 hole 50: 1(0,0)
  round 100 hole 50: 2(138,0)
  silkscreen extent -93,-161 215,113, body extent -69,-150 207,106, height 323
WE-LQS_6045 [mm] "SMD, 2-Leads, Body 6x 6mm, Pitch 4.6mm"
  rect 1.8x5.7 smd: 1(-2.3,0) 2(2.3,0)
  silkscreen extent -2.5,-3.15 2.5,3.15, body extent -3.15,-3.15 3.15,3.15, height 4.5
WE-SPC_4838 [mm] "WURTH"
  rect 2x5.3 smd: 1(-1.75,0) 2(1.75,0)
  silkscreen extent -0.48,-2.65 0.48,2.65, body extent -2.55,-2.55 2.55,2.55, height 4.1

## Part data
C1 C2 C3 C4 C15 C16 C21 C22 C23 C24 C35 C36 C49 C68: "CAP, CERM, 10 µF, 50 V, +/- 10%, X7R, 1210"
C5 C6 C7 C8 C25 C26 C27 C28 C41 C44 C56 C57 C66 C67: "CAP, CERM, 0.1uF, 50V, +/-10%, X7R, 0603"
C9 C10 C11 C12 C13 C14 C17 C18 C19 C20 C29 C30 C31 C32 C33 C34 C37 C38 C39 C40 C42 C52 C53 C54 C55 C62 C63 C64 C65: "CAP, CERM, 1uF, 50V, +/-10%, X7R, 0603"
C43: "CAP, CERM, 200pF, 50V, +/-5%, C0G/NP0, 0603"
C45: "CAP, CERM, 3300 pF, 100 V, +/- 5%, X7R, 0603"
C46: "CAP, CERM, 2.2 µF, 100 V, +/- 10%, X7R, 1206_190"
C47: "CAP, CERM, 100 pF, 100 V, +/- 5%, C0G/NP0, AEC-Q200 Grade 1, 0603"
C48: "CAP, CERM, 0.033 µF, 50 V, +/- 10%, X7R, 0603"
C50 C51 C60 C61: library part GRM1885C1H222JA01D
C58 C59 C69 C70: "CAP, CERM, 0.22 µF, 50 V, +/- 10%, X7R, 0603"
D1 D2 D3 D4 D9 D10 D11 D12: "Diode, Schottky, 60V, 1A, SOD-123"
D5 D6 D7 D8 D13 D14 D15 D16 D19 D20 D23 D24: "Diode, TVS, Bi, 36V, 400W, SOD323, 2-Leads, Body 1.9x1.45mm, No Polarity Mark"
D17 D18 D21 D22: "Diode, Switching, 75V, 0.3A, SOT-23"
FB9 FB10 FB11 FB12: "Ferrite Bead, 600 ohm @ 100 MHz, 3 A, 1210"
FID1 FID2 FID3: "Fiducial mark.  There is nothing to buy or mount."
J1 J2 J4 J5 J6: "Terminal Block, 3.5mm Pitch, 2x1, TH"
J3: library part 851-43-010-20-001000, "Receptacle, 50mil 10x1, R/A, TH"
L1 L2 L3 L4: "Inductor, Shielded Drum Core, Ferrite, 100 µH, 0.52 A, 0.77 ohm, SMD"
L5: "Inductor, Wirewound, Ferrite, 10 µH, 2.45 A, 0.048 ohm, SMD"
Logo2: library part Pb-Free
R1 R2 R3 R4 R5 R6 R7 R8 R30 R31 R32 R33 R34 R35 R36 R37: "RES, 10.0 ohm, 1%, 0.1W, 0603"
R9: "RES, 487 k, 1%, 0.1 W, 0603"
R10 R14: "RES, 10k ohm, 5%, 0.1W, 0603"
R11 R15: "RES, 301 k, 1%, 0.1 W, 0603"
R12 R16: "RES, 0, 5%, 0.1 W, 0603"
R13: "RES, 34.0 k, 1%, 0.1 W, 0603"
R17 R18 R19 R20 R21 R22 R23 R24 R25 R26 R27 R28: "RES, 15 ohm, 5%, 0.1W, 0603"
U1: "Quad-Channel, 16-Bit Programmable Current Output and Voltage Output Digital-to-Analog Converter with Adaptive Power Management, RMP0072A"
U2: "3.5-V to 65-V Input, 500-mA Output, Ultra-Low Quiescent Synchronous Step-Down DC/DC Voltage Regulator, DRC0010J"
ZZ1 ZZ2 ZZ3: library part AssemblyNote

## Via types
v1: diameter 26, hole 10, Top Layer to Bottom Layer, 226 vias
v2: diameter 19.68, hole 7.87, Top Layer to Bottom Layer, 53 vias

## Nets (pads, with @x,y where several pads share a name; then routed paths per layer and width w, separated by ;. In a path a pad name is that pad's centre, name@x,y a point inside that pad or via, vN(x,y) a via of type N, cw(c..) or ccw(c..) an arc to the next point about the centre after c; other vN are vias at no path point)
ALARM: J3.9 R14.1 U1.67 | length 2906.1
  Top Layer w10: v1(510,1330) R14.1@510,1388.5 ; U1.67@1692.91,1668.9 1739.23,1668.9 1745.79,1662.35 1842.35,1662.35 v1(1880,1700) v1@1872.2,1700
  Bottom Layer w10: J3.9@60,1375 320,1375 385,1310 510,1310 ; v1(510,1330) 510,1310 ; v1(1880,1700) 1880,1783.41 1895.87,1799.28 1895.87,1844.13 1820,1920 1520.56,1920 1474.3,1873.75 948.47,1873.75 892.16,1817.44 892.16,1808.76 869.28,1785.87 864.28,1785.87 849.13,1770.72 849.13,1749.28 859.09,1739.32 859.09,1739.09 884.88,1713.29 884.88,1324.88 870,1310 510,1310
CCOMP_A: C50.2 U1.30 | length 1440.1
  Top Layer w10: C50.2@489.7,822 489.7,952 509.7,972 919.7,972 950,1002.3 950,1420 970,1440 1121.67,1440 1232.45,1550.79 U1.30@1307.09,1550.79
CCOMP_B: C51.2 U1.28 | length 1023.7
  Top Layer w10: v1(1016.25,1483.75) 1016.25,1496.25 1127.36,1496.25 1221.27,1590.16 U1.28@1307.09,1590.16 ; C51.2@1039.7,823.5 v1(1039.7,882)
  Bottom Layer w10: 1001.83,1334.95 1001.83,954.6 1019.7,936.72 1019.7,902 v1(1039.7,882) ; 1002.13,1335.25 1016.25,1349.38 v1(1016.25,1483.75)
CCOMP_C: C60.2 U1.63 | length 1006.4
  Top Layer w10: U1.63@1692.91,1590.16 1854.57,1590.16 1892.6,1552.13 1937.87,1552.13 v1(1950,1540) ; C60.2@1949.7,811.55 v1(1949.7,872)
  Bottom Layer w10: v1(1949.7,872) 1949.7,1539.7 v1(1950,1540)
CCOMP_D: C61.2 U1.61 | length 1517.2
  Top Layer w10: U1.61@1692.91,1550.79 1843.38,1550.79 1902.04,1492.13 1997.87,1492.13 2022.13,1467.87 2022.13,1362.6 2062.6,1322.13 2537.87,1322.13 2551.32,1308.68 C61.2@2551.32,811.85
DIG_DVDD: J3.5
DVDD: C43.1 R10.2 R14.2 U1.66 | length 2564.4
  Top Layer w10: R10.2@450,1451.5 v1(450,1500) ; R14.2@510,1451.5 v1(510,1500) ; U1.66@1692.91,1649.21 1720.79,1649.21 1740,1630 C43.1@1898.5,1630 ; v1(1890,1660) 1906,1644 1906,1622.5 C43.1@1908.5,1620
  Bottom Layer w10: v1(450,1500) v1(510,1500) 850,1500 867.01,1517.01 867.01,1700 840,1727.01 840,1733.13 831.25,1741.88 831.25,1778.12 840,1786.87 840,1790.87 1072.88,2023.75 1756.25,2023.75 1960,1820 1960,1730 v1(1890,1660)
GND: C1.1 C2.2 C3.1 C4.2 C5.1 C6.2 C7.1 C8.2 C9.1 C10.2 C11.1 C12.2 C13.2 C14.2 C15.2 C16.2 C17.1 C18.2 C19.1 C20.2 C21.1 C22.2 C23.1 C24.2 C25.1 C26.2 C27.1 C28.2 C29.1 C30.2 C31.1 C32.2 C33.2 C34.2 C35.2 C36.2 C37.1 C38.2 C39.1 C40.2 C41.1 C42.1 C43.2 C44.2 C46.2 C48.2 C49.2 C52.1 C53.1 C54.1 C55.1 C56.2 C57.2 C58.1 C59.1 C62.1 C63.1 C64.1 C65.1 C66.2 C67.2 C68.2 C69.1 C70.1 D5.1 D6.1 D7.1 D8.1 D13.1 D14.1 D15.1 D16.1 D19.1 D20.1 D23.1 D24.1 J1.2 J2.2 J3.3 J4.2 J5.2 J6.1 R13.1 R15.1 R16.1 U1.3 U1.7 U1.9 U1.11 U1.15 U1.18 U1.23 U1.26 U1.32 U1.34 U1.35 U1.45 U1.56 U1.57 U1.59 U1.69 U1.72 U1.73 U2.9 U2.10 U2.11 | length 5935.8
  Top Layer w10: D5.1@410,1606.69 453.31,1606.69 v1(460,1600) 471.53,1600 484.33,1612.8 484.33,1637.5 C9.1@486.83,1640 ; v1(429.7,722) C58.1@429.7,760.5 ; v1(440,2000) C1.1@485.04,2000 ; C5.1@549.82,1760 v1(590,1760) ; C2.2@660,1645.04 660,1600 v1(640,1580) C6.2@738.5,1580 ; C56.2@671.2,502 v1(719.7,502) ; v1(680,1430) D6.1@716.69,1430 ; D19.1@693.01,412 v1(729.7,412) ; v1(709.7,582) C53.1@748.2,582 ; C52.1@738.2,822 v1(738.2,860.5) ; v1(770,2106.69) D8.1@806.69,2106.69 ; v1(774.45,2192.29) C8.2@822.96,2192.29 ; C12.2@885.95,2312.29 v1(885.95,2355.95) ; v1(901.5,2505.95) C11.1@940,2505.95 ; C15.2@940,1635.04 993.15,1635.04 v1(993.15,1638.03) ; C4.2@955.04,2290 v1(955.04,2354.96) ; v1(979.7,722) C59.1@979.7,760.5 ; C14.2@1040,1748.5 C14.2@1048.5,1740 1048.5,1778.5 1098.5,1778.5 v1(1130,1810) C13.2@1170.45,1810 ; v1(1060,1540) 1070,1550 1130.56,1550 1210.08,1629.53 U1.26@1307.09,1629.53 ; v1(1060,2394.45) C7.1@1060,2442.95 ; v1(1070,1620) 1080,1630 1130.56,1630 1189.14,1688.58 U1.23@1307.09,1688.58 ; v1(1080,1310) C17.1@1158.5,1310 ; v1(1080,1380) C18.2@1158.5,1380 1190,1411.5 v1(1190,1430) ; D7.1@1083.31,2584.45 v1(1120,2584.45) ; C16.2@1170,2154.96 v1(1170,2200) ; v1(1190,1240) C20.2@1238.5,1240 ; C57.2@1221.2,502 v1(1259.7,502) ; v1(1240,1170) C19.1@1278.5,1170 ; D20.1@1243.01,412 v1(1279.7,412) ; v1(1249.7,582) C55.1@1288.2,582 ; C54.1@1288.2,822 v1(1288.2,860.5) ; v1(1300,1830) 1320,1830 1332.68,1817.32 U1.18@1332.68,1792.91 ; C3.1@1300,2514.96 v1(1300,2560) ; U1.35@1307.09,1452.36 1272.36,1452.36 ; U1.34@1307.09,1472.05 1292.05,1472.05 1272.36,1452.36 ; U1.32@1307.09,1511.42 1246.69,1511.42 1190,1454.72 v1(1190,1430) ; v1(1310,1900) 1330,1900 1391.73,1838.27 U1.15@1391.73,1792.91 ; v1(1370,1980) 1370,1965.28 1470.47,1864.81 U1.11@1470.47,1792.91 ; v1(1430,1130) 1461.5,1130 C41.1@1470,1138.5 C42.1@1530,1138.5 C44.2@1590,1138.5 ; v1(1470,1930) 1509.84,1890.16 U1.9@1509.84,1792.91 ; U1.45@1490.16,1407.09 1490.16,1269.84 v1(1500,1260) ; U1.7@1549.21,1792.91 1549.21,1949.21 v1(1570,1970) ; U1.3@1627.95,1792.91 1627.95,1833.23 1684.72,1890 v1(1684.72,1893.75) ; C63.1@1691.2,812 v1(1691.2,850.5) ; U1.56@1692.91,1452.36 U1.57@1692.91,1472.05 1797.95,1472.05 1810,1460 1810,1421.5 C40.2@1821.5,1410 v1(1851.02,1410) v1@1860,1410 ; U1.59@1692.91,1511.42 1818.58,1511.42 1900,1430 v1(1980,1430) ; U1.69@1692.91,1708.27 1758.27,1708.27 1760,1710 v1(1763.91,1706.09) ; U1.72@1692.91,1767.32 1717.32,1767.32 v1(1730,1780) ; C62.1@1701.2,572 v1(1739.7,572) ; v1(1709.7,412) D23.1@1746.39,412 ; v1(1719.7,502) C66.2@1768.2,502 ; v1(1750,1040) C37.1@1750,1088.5 ; C35.2@1820,2154.96 v1(1820,2190) ; C38.2@1821.5,1270 v1(1870,1270) ; C39.1@1821.5,1340 v1(1870,1340) ; C34.2@1831.5,1810 v1(1870,1810) 1870,1758.5 C33.2@1861.5,1750 ; v1(1940,2410) C25.1@1940,2448.5 ; C43.2@1971.5,1620 v1(2020,1620) ; v1(2009.7,702) C69.1@2009.7,748.56 ; C22.2@2044.96,2290 v1(2044.96,2354.96) ; C36.2@2054.96,1720 v1(2090,1720) ; C29.1@2060,2511.5 v1(2060,2550) ; D16.1@2090,1416.69 2126.69,1416.69 2140.02,1430.02 2140.02,1440 C32.2@2168.5,1440 ; C30.2@2118.5,2320 2118.5,2358.5 v1(2120,2360) ; C26.2@2181.5,2200 v1(2230,2200) ; C28.2@2231.5,1560 v1(2270,1560) 2310,1600 C24.2@2310,1625.04 ; v1(2289.7,862) 2291.2,860.5 C65.1@2291.2,812 ; C64.1@2301.2,572 v1(2339.7,572) ; v1(2309.7,412) D24.1@2346.39,412 ; v1(2329.7,502) C67.2@2368.2,502 ; v1(2390,1740) C27.1@2438.5,1740 ; C31.1@2501.5,1620 2501.5,1581.5 2503.03,1579.96 2580,1579.96 D15.1@2580,1596.69 ; v1(2609.7,712) 2611.02,713.32 C70.1@2611.02,748.56 ; v1(1190,1430) 1250,1430 1272.36,1452.36
  Bottom Layer w10: v1(1684.72,1893.75) v1@1686.25,1893.75
  other v1: 100,100 200,100 300,100 400,100 500,100 900,100 1000,100 1400,100 1500,100 1600,100 1700,100 2100,100 2200,100 2300,100 2700,100 2800,100 2900,100 3000,100 3100,100 100,200 3100,200 100,300 3100,300 100,400 3100,400 100,500 3100,500 100,600 3100,600 100,700 3100,700 100,800 3100,800 3100,900 3100,1000 3100,1100 800,1103 3100,1200 3100,1300 3100,1400 100,1550 2500,1580 100,1650 100,1750 100,1850 100,1950 3100,1950 100,2050 3100,2050 2040,2060 940,2065 100,2150 3100,2150 1370,2240 1620,2240 100,2250 3100,2250 100,2350 3100,2350 100,2450 3100,2450 100,2550 3100,2550 100,2650 200,2650 300,2650 400,2650 500,2650 600,2650 700,2650 800,2650 900,2650 1000,2650 1100,2650 1200,2650 1300,2650 1400,2650 1500,2650 1600,2650 1700,2650 1800,2650 1900,2650 2000,2650 2100,2650 2200,2650 2300,2650 3100,2650
  other v2: 1344.68,1444.68 1396.46,1444.68 1448.23,1444.68 1500,1444.68 1551.77,1444.68 1603.54,1444.68 1655.32,1444.68 1344.68,1496.46 1396.46,1496.46 1448.23,1496.46 1500,1496.46 1551.77,1496.46 1603.54,1496.46 1655.32,1496.46 1344.68,1548.23 1396.46,1548.23 1448.23,1548.23 1500,1548.23 1551.77,1548.23 1603.54,1548.23 1655.32,1548.23 1344.68,1600 1396.46,1600 1448.23,1600 1500,1600 1551.77,1600 1603.54,1600 1655.32,1600 1344.68,1651.77 1396.46,1651.77 1448.23,1651.77 1500,1651.77 1551.77,1651.77 1603.54,1651.77 1655.32,1651.77 1344.68,1703.54 1396.46,1703.54 1448.23,1703.54 1500,1703.54 1551.77,1703.54 1603.54,1703.54 1655.32,1703.54 1344.68,1755.32 1396.46,1755.32 1448.23,1755.32 1500,1755.32 1551.77,1755.32 1603.54,1755.32 1655.32,1755.32 2930,2262.36 2892.6,2285 2967.4,2285 2930,2307.64
HART_IN_A: C58.2 U1.29 | length 1514.5
  Top Layer w10: C58.2@429.7,823.5 429.7,972 449.7,992 903,992 930,1019 930,1374.41 930.31,1374.72 930.31,1430.31 957.87,1457.87 1114.26,1457.87 1226.86,1570.47 U1.29@1307.09,1570.47
HART_IN_B: C59.2 U1.27 | length 1055.1
  Top Layer w10: C59.2@979.7,823.5 v1(979.7,882) ; v1(980,1510) 984.13,1514.13 1119.96,1514.13 1215.68,1609.84 U1.27@1307.09,1609.84
  Bottom Layer w10: v1(979.7,882) 979.7,1509.7 v1(980,1510)
HART_IN_C: C69.2 U1.64 | length 1092.2
  Top Layer w10: U1.64@1692.91,1609.84 1860.16,1609.84 1900,1570 v1(2010,1570) ; C69.2@2009.7,811.55 v1(2009.7,872)
  Bottom Layer w10: v1(2009.7,872) 2009.7,1569.7 v1(2010,1570)
HART_IN_D: C70.2 U1.62 | length 1588.1
  Top Layer w10: U1.62@1692.91,1570.47 1848.97,1570.47 1885.19,1534.25 1915.75,1534.25 1940,1510 2010,1510 2040,1480 2040,1370 2070,1340 2580,1340 2610,1310 C70.2@2610,813.17 ; C70.2@2609.7,812.87 C70.2@2611.02,811.55
IOUT_A: R21.1 U1.37 | length 1240.9
  Top Layer w10: R21.1@609.7,822 609.7,932 631.83,954.13 930.08,954.13 967.87,991.92 967.87,1337.87 978.43,1348.43 1288.43,1348.43 1332.68,1392.68 U1.37@1332.68,1407.09
IOUT_B: R22.1 U1.41 | length 762.9
  Top Layer w10: R22.1@1159.7,823.5 1160,823.8 1160,1170 1198.43,1208.43 1326.51,1208.43 1334.06,1215.97 1334.06,1234.06 1411.42,1311.42 U1.41@1411.42,1407.09
IOUT_C: R27.1 U1.50 | length 721.8
  Top Layer w10: U1.50@1588.58,1407.09 1588.58,1356.14 1706.3,1238.43 1751.57,1238.43 1830,1160 R27.1@1830,811.85
IOUT_D: R28.1 U1.54 | length 1280.7
  Top Layer w10: U1.54@1667.32,1407.09 1667.32,1392.68 1681.57,1378.43 1955.74,1378.43 2052.04,1282.13 2407.87,1282.13 2431.32,1258.68 R28.1@2431.32,811.85
LN_A: D1.2 L1.1 U1.14 | length 708.4
  Top Layer w10: D1.2@814.47,1990 815.57,1988.9 L1.1@970,1988.9 1111.1,1988.9 1161.1,1938.9 1316.38,1938.9 1411.42,1843.86 U1.14@1411.42,1792.91
LN_B: D2.2 L2.1 U1.10 | length 495.9
  Top Layer w10: D2.2@1438.9,2264.43 D2.2@1440,2265.53 1440,2111.1 L2.1@1438.9,2110 1438.9,1921.66 1490.16,1870.4 U1.10@1490.16,1792.91
LN_C: D9.2 L3.1 U1.8 | length 472.7
  Top Layer w10: U1.8@1529.53,1792.91 1529.53,2088.43 L3.1@1551.1,2110 D9.2@1551.1,2256.63
LN_D: D10.2 L4.1 U1.4 | length 685.4
  Top Layer w10: U1.4@1608.27,1792.91 1608.27,1858.27 1706,1956 L4.1@2005.1,1956 ; L4.1@2001.1,1970 L4.1@2020,1988.9 2174.43,1988.9 D10.2@2175.53,1990
LP_A: D3.1 L1.2 U1.16 | length 625
  Top Layer w10: D3.1@814.47,1860 823.37,1851.1 L1.2@970,1851.1 1081.1,1851.1 1103.75,1873.75 1326.81,1873.75 1372.05,1828.51 U1.16@1372.05,1792.91
LP_B: D4.1 L2.2 U1.12 | length 560.5
  Top Layer w10: D4.1@1304.47,2290 1301.1,2286.63 L2.2@1301.1,2110 1301.1,2008.9 1450.79,1859.21 U1.12@1450.79,1792.91
LP_C: D11.1 L3.2 U1.6 | length 548.2
  Top Layer w10: U1.6@1568.9,1792.91 1568.9,1918.9 1688.9,2038.9 L3.2@1688.9,2110 1688.9,2286.63 D11.1@1685.53,2290
LP_D: D12.1 L4.2 U1.2 | length 587.6
  Top Layer w10: U1.2@1647.64,1792.91 1647.64,1827.64 1687.87,1867.87 1873.99,1867.87 1891.87,1850 2018.9,1850 L4.2@2020,1851.1 2174.43,1851.1 D12.1@2175.53,1850
NetC1_2: C1.2 D1.1 R30.2 | length 200.6
  Top Layer w10: 614.96,1860 614.96,1990 D1.1@685.53,1990
NetC2_1: C2.1 D3.2 R31.2 | length 227
  Top Layer w10: C2.1@660,1774.96 800,1774.96 ; C2.1@685,1773 D3.2@685.53,1860
NetC3_2: C3.2 D2.1 R32.2 | length 283.9
  Top Layer w10: 1160,2385.04 C3.2@1300,2385.04 1309.43,2394.47 D2.1@1440,2394.47
NetC4_1: C4.1 D4.2 R33.2 | length 230.6
  Top Layer w10: R33.2@1084.96,2150 C4.1@1084.96,2290 D4.2@1175.53,2290
NetC9_2: C9.2 R1.1 | length 60
  Top Layer w10: C9.2@549.82,1640 R1.1@549.82,1700
NetC10_1: C10.1 R2.2 | length 57
  Top Layer w10: C10.1@680,1518.5 R2.2@737.01,1518.5
NetC11_2: C11.2 R3.1 | length 60
  Top Layer w10: C11.2@940,2442.95 R3.1@1000,2442.95
NetC12_1: C12.1 R4.2 | length 60
  Top Layer w10: R4.2@822.96,2252.29 C12.1@822.96,2312.29
NetC21_2: C21.2 D9.1 R34.2 | length 283.9
  Top Layer w10: D9.1@1560,2394.47 1569.43,2385.04 C21.2@1700,2385.04 1840,2385.04
NetC22_1: C22.1 D11.2 R35.2 | length 240.6
  Top Layer w10: D11.2@1814.47,2290 C22.1@1915.04,2290 R35.2@1915.04,2150
NetC23_2: C23.2 D10.1 R36.2 | length 210.6
  Top Layer w10: D10.1@2304.47,1990 C23.2@2375.04,1990 2375.04,1850
NetC24_1: C24.1 D12.2 R37.2 | length 237.3
  Top Layer w10: 2170,1754.96 C24.1@2310,1754.96 2304.47,1760.49 D12.2@2304.47,1850
NetC29_2: C29.2 R5.1 | length 60
  Top Layer w10: R5.1@2000,2448.5 C29.2@2060,2448.5
NetC30_1: C30.1 R6.2 | length 60
  Top Layer w10: R6.2@2181.5,2260 C30.1@2181.5,2320
NetC31_2: C31.2 R7.1 | length 60
  Top Layer w10: C31.2@2438.5,1620 R7.1@2438.5,1680
NetC32_1: C32.1 R8.2 | length 60
  Top Layer w10: C32.1@2231.5,1440 R8.2@2231.5,1500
